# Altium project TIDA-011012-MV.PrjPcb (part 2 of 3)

## Sheet TIDA-011012-MV Communication.SchDoc
size 431 x 279 mm; Date: Not shown in title block; ApprovedBy: Not shown in title block; CheckedBy: Not shown in title block; Author: Not shown in title block; CompanyName: Not shown in title block; Engineer: Not shown in title block; Organization: Not shown in title block; Address1: Not shown in title block; Address2: Not shown in title block; Address3: Not shown in title block; Address4: Not shown in title block; DocumentNumber: 3; Revision: Use project parameter SCH_Rev; SheetNumber: 3; SheetTotal: 11; PageSetup: Record=PageOptions¦CenterHorizontal=True¦CenterVertical=True¦PrintScale=1.00¦XCorrection=1.00¦YCorrection=1.00¦PrintKind=0¦BorderSize=5000000¦LeftOffset=0¦BottomOffset=0¦Orientation=2¦PaperLength=1000¦PaperWidth=1000¦Scale=100¦PaperSource=15¦PrintQuality=600¦MediaType=1¦DitherType=10¦PaperKind=Letter¦PrintScaleMode=1
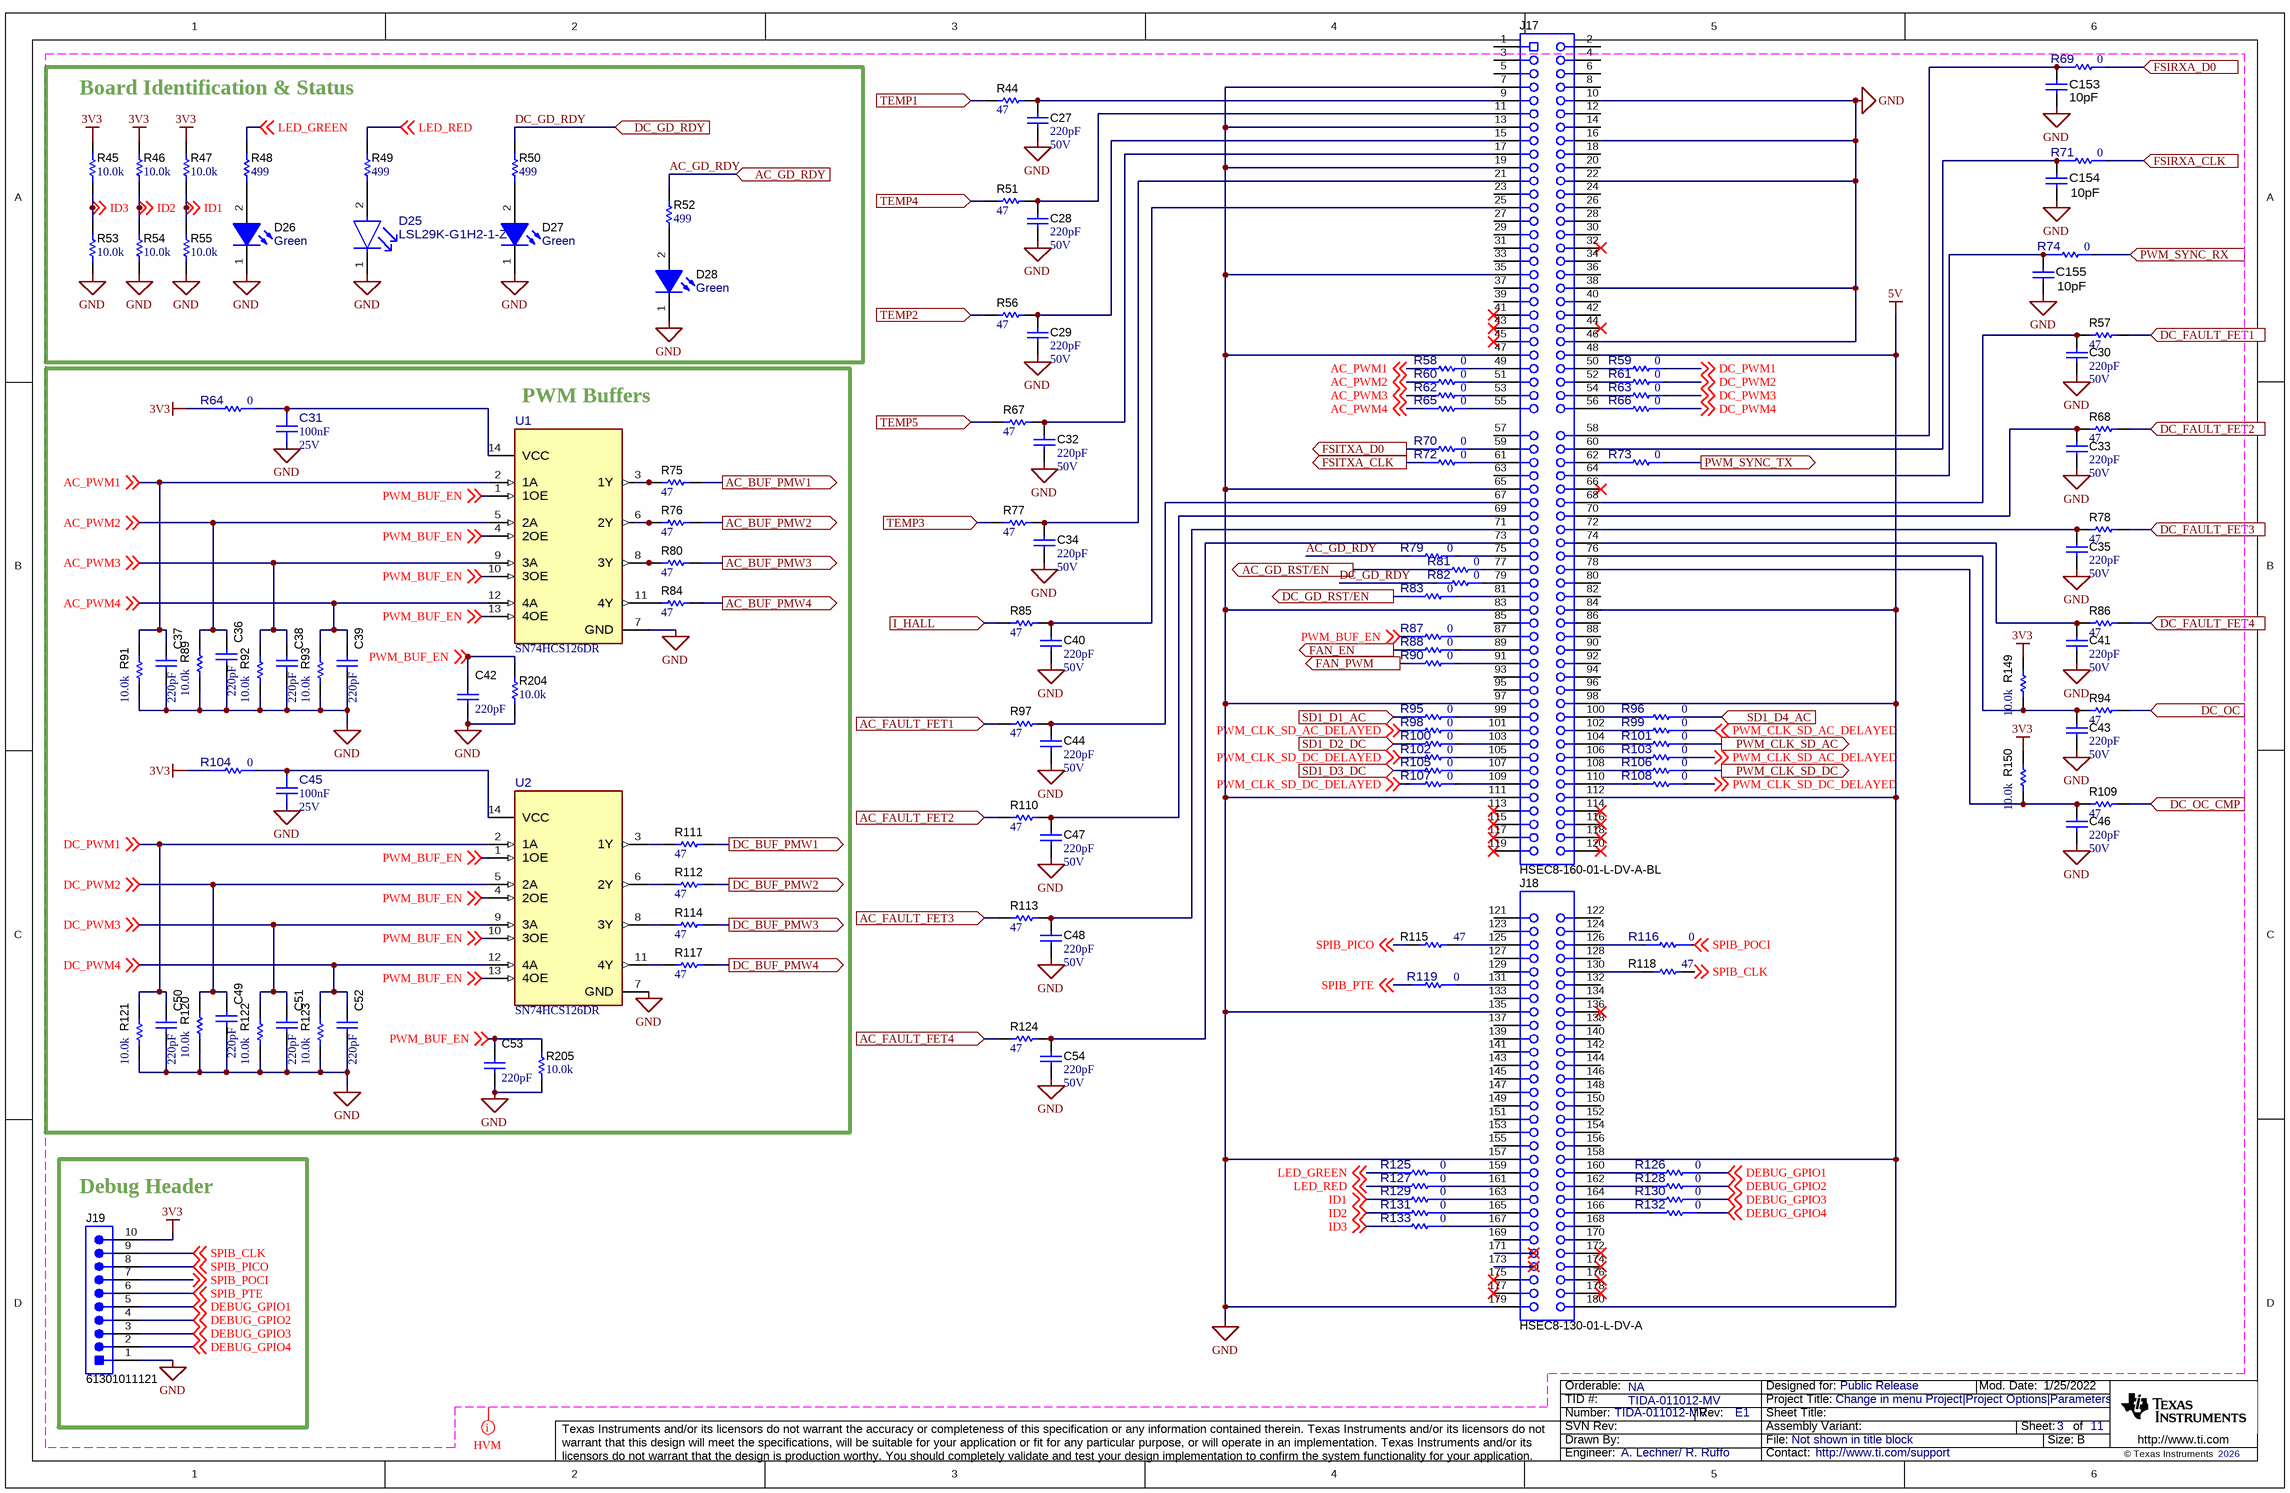
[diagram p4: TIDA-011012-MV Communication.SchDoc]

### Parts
C27  Cap_F: 220pF  VDC_V: 50V  [0603]  (hidden comment: C0603X221K5RACTU)
C28  Cap_F: 220pF  VDC_V: 50V  [0603]  (hidden comment: C0603X221K5RACTU)
C29  Cap_F: 220pF  VDC_V: 50V  [0603]  (hidden comment: C0603X221K5RACTU)
C30  Cap_F: 220pF  VDC_V: 50V  [0603]  (hidden comment: C0603X221K5RACTU)
C31  Cap_F: 100nF  VDC_V: 25V  [FP-GMC10X7R104K25NT_0603-MFG]  (hidden comment: GMC10X7R104K25NT)
C32  Cap_F: 220pF  VDC_V: 50V  [0603]  (hidden comment: C0603X221K5RACTU)
C33  Cap_F: 220pF  VDC_V: 50V  [0603]  (hidden comment: C0603X221K5RACTU)
C34  Cap_F: 220pF  VDC_V: 50V  [0603]  (hidden comment: C0603X221K5RACTU)
C35  Cap_F: 220pF  VDC_V: 50V  [0603]  (hidden comment: C0603X221K5RACTU)
C36  Cap_F: 220pF  [0603]  (hidden comment: C0603X221K5RACTU)
C37  Cap_F: 220pF  [0603]  (hidden comment: C0603X221K5RACTU)
C38  Cap_F: 220pF  [0603]  (hidden comment: C0603X221K5RACTU)
C39  Cap_F: 220pF  [0603]  (hidden comment: C0603X221K5RACTU)
C40  Cap_F: 220pF  VDC_V: 50V  [0603]  (hidden comment: C0603X221K5RACTU)
C41  Cap_F: 220pF  VDC_V: 50V  [0603]  (hidden comment: C0603X221K5RACTU)
C42  Cap_F: 220pF  [0603]  (hidden comment: C0603X221K5RACTU)
C43  Cap_F: 220pF  VDC_V: 50V  [0603]  (hidden comment: C0603X221K5RACTU)
C44  Cap_F: 220pF  VDC_V: 50V  [0603]  (hidden comment: C0603X221K5RACTU)
C45  Cap_F: 100nF  VDC_V: 25V  [FP-GMC10X7R104K25NT_0603-MFG]  (hidden comment: GMC10X7R104K25NT)
C46  Cap_F: 220pF  VDC_V: 50V  [0603]  (hidden comment: C0603X221K5RACTU)
C47  Cap_F: 220pF  VDC_V: 50V  [0603]  (hidden comment: C0603X221K5RACTU)
C48  Cap_F: 220pF  VDC_V: 50V  [0603]  (hidden comment: C0603X221K5RACTU)
C49  Cap_F: 220pF  [0603]  (hidden comment: C0603X221K5RACTU)
C50  Cap_F: 220pF  [0603]  (hidden comment: C0603X221K5RACTU)
C51  Cap_F: 220pF  [0603]  (hidden comment: C0603X221K5RACTU)
C52  Cap_F: 220pF  [0603]  (hidden comment: C0603X221K5RACTU)
C53  Cap_F: 220pF  [0603]  (hidden comment: C0603X221K5RACTU)
C54  Cap_F: 220pF  VDC_V: 50V  [0603]  (hidden comment: C0603X221K5RACTU)
C153  Cap_F: 10pF  [0603]  (hidden comment: 0603ZC100KAT2A)
C154  Cap_F: 10pF  [0603]  (hidden comment: 0603ZC100KAT2A)
C155  Cap_F: 10pF  [0603]  (hidden comment: 0603ZC100KAT2A)
D25  LSL29K-G1H2-1-Z  [FP-LSL29K-G1H2-1-Z_0603-0]
D26  value Green  [WL-SMCW_GREEN]  (hidden comment: 150060VS75000)
D27  value Green  [WL-SMCW_GREEN]  (hidden comment: 150060VS75000)
D28  value Green  [WL-SMCW_GREEN]  (hidden comment: 150060VS75000)
J17  HSEC8-160-01-L-DV-A-BL  [controlCARD-120HSEC]
J18  HSEC8-130-01-L-DV-A  [controlCARD-180HSEC-60pinAddon]
J19  61301011121  [Wurth_61301011121]
R44  ValueDisplayed: 47  [0603]  (hidden comment: ERJ-3GEYJ470V)
R45  ValueDisplayed: 10.0k  [0603]  (hidden comment: ERJ-3EKF1002V)
R46  ValueDisplayed: 10.0k  [0603]  (hidden comment: ERJ-3EKF1002V)
R47  ValueDisplayed: 10.0k  [0603]  (hidden comment: ERJ-3EKF1002V)
R48  ValueDisplayed: 499  [0603]  (hidden comment: CRCW0603499RFKEAC)
R49  ValueDisplayed: 499  [0603]  (hidden comment: CRCW0603499RFKEAC)
R50  ValueDisplayed: 499  [0603]  (hidden comment: CRCW0603499RFKEAC)
R51  ValueDisplayed: 47  [0603]  (hidden comment: ERJ-3GEYJ470V)
R52  ValueDisplayed: 499  [0603]  (hidden comment: CRCW0603499RFKEAC)
R53  ValueDisplayed: 10.0k  [0603]  (hidden comment: ERJ-3EKF1002V)
R54  ValueDisplayed: 10.0k  [0603]  (hidden comment: ERJ-3EKF1002V)
R55  ValueDisplayed: 10.0k  [0603]  (hidden comment: ERJ-3EKF1002V)
R56  ValueDisplayed: 47  [0603]  (hidden comment: ERJ-3GEYJ470V)
R57  ValueDisplayed: 47  [0603]  (hidden comment: ERJ-3GEYJ470V)
R58  value 0  [FP-ERJ-H3G0R00V_0603-MFG]  (hidden comment: ERJ-H3G0R00V)
R59  value 0  [FP-ERJ-H3G0R00V_0603-MFG]  (hidden comment: ERJ-H3G0R00V)
R60  value 0  [FP-ERJ-H3G0R00V_0603-MFG]  (hidden comment: ERJ-H3G0R00V)
R61  value 0  [FP-ERJ-H3G0R00V_0603-MFG]  (hidden comment: ERJ-H3G0R00V)
R62  value 0  [FP-ERJ-H3G0R00V_0603-MFG]  (hidden comment: ERJ-H3G0R00V)
R63  value 0  [FP-ERJ-H3G0R00V_0603-MFG]  (hidden comment: ERJ-H3G0R00V)
R64  value 0  [FP-ERJ-H3G0R00V_0603-MFG]  (hidden comment: ERJ-H3G0R00V)
R65  value 0  [FP-ERJ-H3G0R00V_0603-MFG]  (hidden comment: ERJ-H3G0R00V)
R66  value 0  [FP-ERJ-H3G0R00V_0603-MFG]  (hidden comment: ERJ-H3G0R00V)
R67  ValueDisplayed: 47  [0603]  (hidden comment: ERJ-3GEYJ470V)
R68  ValueDisplayed: 47  [0603]  (hidden comment: ERJ-3GEYJ470V)
R69  value 0  [FP-ERJ-H3G0R00V_0603-MFG]  (hidden comment: ERJ-H3G0R00V)
R70  value 0  [FP-ERJ-H3G0R00V_0603-MFG]  (hidden comment: ERJ-H3G0R00V)
R71  value 0  [FP-ERJ-H3G0R00V_0603-MFG]  (hidden comment: ERJ-H3G0R00V)
R72  value 0  [FP-ERJ-H3G0R00V_0603-MFG]  (hidden comment: ERJ-H3G0R00V)
R73  value 0  [FP-ERJ-H3G0R00V_0603-MFG]  (hidden comment: ERJ-H3G0R00V)
R74  value 0  [FP-ERJ-H3G0R00V_0603-MFG]  (hidden comment: ERJ-H3G0R00V)
R75  ValueDisplayed: 47  [0603]  (hidden comment: ERJ-3GEYJ470V)
R76  ValueDisplayed: 47  [0603]  (hidden comment: ERJ-3GEYJ470V)
R77  ValueDisplayed: 47  [0603]  (hidden comment: ERJ-3GEYJ470V)
R78  ValueDisplayed: 47  [0603]  (hidden comment: ERJ-3GEYJ470V)
R79  value 0  [FP-ERJ-H3G0R00V_0603-MFG]  (hidden comment: ERJ-H3G0R00V)
R80  ValueDisplayed: 47  [0603]  (hidden comment: ERJ-3GEYJ470V)
R81  value 0  [FP-ERJ-H3G0R00V_0603-MFG]  (hidden comment: ERJ-H3G0R00V)
R82  value 0  [FP-ERJ-H3G0R00V_0603-MFG]  (hidden comment: ERJ-H3G0R00V)
R83  value 0  [FP-ERJ-H3G0R00V_0603-MFG]  (hidden comment: ERJ-H3G0R00V)
R84  ValueDisplayed: 47  [0603]  (hidden comment: ERJ-3GEYJ470V)
R85  ValueDisplayed: 47  [0603]  (hidden comment: ERJ-3GEYJ470V)
R86  ValueDisplayed: 47  [0603]  (hidden comment: ERJ-3GEYJ470V)
R87  value 0  [FP-ERJ-H3G0R00V_0603-MFG]  (hidden comment: ERJ-H3G0R00V)
R88  value 0  [FP-ERJ-H3G0R00V_0603-MFG]  (hidden comment: ERJ-H3G0R00V)
R89  ValueDisplayed: 10.0k  [0603]  (hidden comment: ERJ-3EKF1002V)
R90  value 0  [FP-ERJ-H3G0R00V_0603-MFG]  (hidden comment: ERJ-H3G0R00V)
R91  ValueDisplayed: 10.0k  [0603]  (hidden comment: ERJ-3EKF1002V)
R92  ValueDisplayed: 10.0k  [0603]  (hidden comment: ERJ-3EKF1002V)
R93  ValueDisplayed: 10.0k  [0603]  (hidden comment: ERJ-3EKF1002V)
R94  ValueDisplayed: 47  [0603]  (hidden comment: ERJ-3GEYJ470V)
R95  value 0  [FP-ERJ-H3G0R00V_0603-MFG]  (hidden comment: ERJ-H3G0R00V)
R96  value 0  [FP-ERJ-H3G0R00V_0603-MFG]  (hidden comment: ERJ-H3G0R00V)
R97  ValueDisplayed: 47  [0603]  (hidden comment: ERJ-3GEYJ470V)
R98  value 0  [FP-ERJ-H3G0R00V_0603-MFG]  (hidden comment: ERJ-H3G0R00V)
R99  value 0  [FP-ERJ-H3G0R00V_0603-MFG]  (hidden comment: ERJ-H3G0R00V)
R100  value 0  [FP-ERJ-H3G0R00V_0603-MFG]  (hidden comment: ERJ-H3G0R00V)
R101  value 0  [FP-ERJ-H3G0R00V_0603-MFG]  (hidden comment: ERJ-H3G0R00V)
R102  value 0  [FP-ERJ-H3G0R00V_0603-MFG]  (hidden comment: ERJ-H3G0R00V)
R103  value 0  [FP-ERJ-H3G0R00V_0603-MFG]  (hidden comment: ERJ-H3G0R00V)
R104  value 0  [FP-ERJ-H3G0R00V_0603-MFG]  (hidden comment: ERJ-H3G0R00V)
R105  value 0  [FP-ERJ-H3G0R00V_0603-MFG]  (hidden comment: ERJ-H3G0R00V)
R106  value 0  [FP-ERJ-H3G0R00V_0603-MFG]  (hidden comment: ERJ-H3G0R00V)
R107  value 0  [FP-ERJ-H3G0R00V_0603-MFG]  (hidden comment: ERJ-H3G0R00V)
R108  value 0  [FP-ERJ-H3G0R00V_0603-MFG]  (hidden comment: ERJ-H3G0R00V)
R109  ValueDisplayed: 47  [0603]  (hidden comment: ERJ-3GEYJ470V)
R110  ValueDisplayed: 47  [0603]  (hidden comment: ERJ-3GEYJ470V)
R111  ValueDisplayed: 47  [0603]  (hidden comment: ERJ-3GEYJ470V)
R112  ValueDisplayed: 47  [0603]  (hidden comment: ERJ-3GEYJ470V)
R113  ValueDisplayed: 47  [0603]  (hidden comment: ERJ-3GEYJ470V)
R114  ValueDisplayed: 47  [0603]  (hidden comment: ERJ-3GEYJ470V)
R115  ValueDisplayed: 47  [0603]  (hidden comment: ERJ-3GEYJ470V)
R116  value 0  [FP-ERJ-H3G0R00V_0603-MFG]  (hidden comment: ERJ-H3G0R00V)
R117  ValueDisplayed: 47  [0603]  (hidden comment: ERJ-3GEYJ470V)
R118  ValueDisplayed: 47  [0603]  (hidden comment: ERJ-3GEYJ470V)
R119  value 0  [FP-ERJ-H3G0R00V_0603-IPC_B]  (hidden comment: ERJ-H3G0R00V)
R120  ValueDisplayed: 10.0k  [0603]  (hidden comment: ERJ-3EKF1002V)
R121  ValueDisplayed: 10.0k  [0603]  (hidden comment: ERJ-3EKF1002V)
R122  ValueDisplayed: 10.0k  [0603]  (hidden comment: ERJ-3EKF1002V)
R123  ValueDisplayed: 10.0k  [0603]  (hidden comment: ERJ-3EKF1002V)
R124  ValueDisplayed: 47  [0603]  (hidden comment: ERJ-3GEYJ470V)
R125  value 0  [FP-ERJ-H3G0R00V_0603-MFG]  (hidden comment: ERJ-H3G0R00V)
R126  value 0  [FP-ERJ-H3G0R00V_0603-MFG]  (hidden comment: ERJ-H3G0R00V)
R127  value 0  [FP-ERJ-H3G0R00V_0603-MFG]  (hidden comment: ERJ-H3G0R00V)
R128  value 0  [FP-ERJ-H3G0R00V_0603-MFG]  (hidden comment: ERJ-H3G0R00V)
R129  value 0  [FP-ERJ-H3G0R00V_0603-MFG]  (hidden comment: ERJ-H3G0R00V)
R130  value 0  [FP-ERJ-H3G0R00V_0603-MFG]  (hidden comment: ERJ-H3G0R00V)
R131  value 0  [FP-ERJ-H3G0R00V_0603-MFG]  (hidden comment: ERJ-H3G0R00V)
R132  value 0  [FP-ERJ-H3G0R00V_0603-MFG]  (hidden comment: ERJ-H3G0R00V)
R133  value 0  [FP-ERJ-H3G0R00V_0603-MFG]  (hidden comment: ERJ-H3G0R00V)
R149  ValueDisplayed: 10.0k  [0603]  (hidden comment: ERJ-3EKF1002V)
R150  ValueDisplayed: 10.0k  [0603]  (hidden comment: ERJ-3EKF1002V)
R204  ValueDisplayed: 10.0k  [0603]  (hidden comment: ERJ-3EKF1002V)
R205  ValueDisplayed: 10.0k  [0603]  (hidden comment: ERJ-3EKF1002V)
U1  SN74HCS126DR  [D0014A-MFG]
U2  SN74HCS126DR  [D0014A-MFG]

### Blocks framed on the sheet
Board Identification & Status: D25-D28 R45-R50 R52-R55
PWM Buffers: C31 C36-C39 C42 C45 C49-C53 R64 R75 R76 R80 R84 R89 R91-R93 R104 R111 R112 R114 R117 R120-R123 R204 R205 U1 U2
Debug Header: J19

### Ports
AC_BUF_PMW1 (out), AC_BUF_PMW2 (out), AC_BUF_PMW3 (out), AC_BUF_PMW4 (out), AC_FAULT_FET1 (in), AC_FAULT_FET2 (in), AC_FAULT_FET3 (in), AC_FAULT_FET4 (in), AC_GD_RDY (in), AC_GD_RST/EN (out), DC_BUF_PMW1 (out), DC_BUF_PMW2 (out), DC_BUF_PMW3 (out), DC_BUF_PMW4 (out), DC_FAULT_FET1 (in), DC_FAULT_FET2 (in), DC_FAULT_FET3 (in), DC_FAULT_FET4 (in), DC_GD_RDY (in), DC_GD_RST/EN (out), DC_OC (in), DC_OC_CMP (in), FAN_EN (out), FAN_PWM (out), FSIRXA_CLK (in), FSIRXA_D0 (in), FSITXA_CLK (out), FSITXA_D0 (out), I_HALL (in), PWM_CLK_SD_AC (out), PWM_CLK_SD_DC (out), PWM_SYNC_RX (in), PWM_SYNC_TX (out), SD1_D1_AC (in), SD1_D2_DC (in), SD1_D3_DC (in), SD1_D4_AC (in), TEMP1 (in), TEMP2 (in), TEMP3 (in), TEMP4 (in), TEMP5 (in)

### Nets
3V3: J19.10 R45.2 R46.2 R47.2 R64.1 R104.1 R149.2 R150.2
5V: J17.48 J17.84 J17.98 J17.112 J18.158 J18.180
GND: C27.2 C28.2 C29.2 C30.2 C31.1 C32.2 C33.2 C34.2 C35.2 C36.1 C37.1 C38.1 C39.1 C40.2 C41.2 C42.1 C43.2 C44.2 C45.1 C46.2 C47.2 C48.2 C49.1 C50.1 C51.1 C52.1 C53.1 C54.2 C153.2 C154.2 C155.2 D25.1(CATHODE) D26.1(K) D27.1(K) D28.1(K) J17.7 J17.10 J17.13 J17.16 J17.19 J17.22 J17.35 J17.38 J17.46 J17.47 J17.65 J17.83 J17.97 J17.111 J18.135 J18.157 J18.179 J19.1 R53.1 R54.1 R55.1 R89.1 R91.1 R92.1 R93.1 R120.1 R121.1 R122.1 R123.1 R204.1 R205.1 U1.7(GND) U2.7(GND)
AC_BUF_PMW1: R75.2 ; port AC_BUF_PMW1
AC_BUF_PMW2: R76.2 ; port AC_BUF_PMW2
AC_BUF_PMW3: R80.2 ; port AC_BUF_PMW3
AC_BUF_PMW4: R84.2 ; port AC_BUF_PMW4
AC_FAULT_FET1: R97.1 ; port AC_FAULT_FET1
AC_FAULT_FET2: R110.1 ; port AC_FAULT_FET2
AC_FAULT_FET3: R113.1 ; port AC_FAULT_FET3
AC_FAULT_FET4: R124.1 ; port AC_FAULT_FET4
AC_GD_RDY: R52.2 R79.1 ; port AC_GD_RDY
AC_GD_RST/EN: R81.1 ; port AC_GD_RST/EN
AC_PWM1: C37.2 R58.1 R91.2 U1.2(1A) ; off-sheet AC_PWM1
AC_PWM2: C36.2 R60.1 R89.2 U1.5(2A) ; off-sheet AC_PWM2
AC_PWM3: C38.2 R62.1 R92.2 U1.9(3A) ; off-sheet AC_PWM3
AC_PWM4: C39.2 R65.1 R93.2 U1.12(4A) ; off-sheet AC_PWM4
CLK_MOD_AC: R101.1 ; port PWM_CLK_SD_AC
CLK_MOD_DC: R106.1 ; port PWM_CLK_SD_DC
DATA_I_AC: R95.1 ; port SD1_D1_AC
DATA_I_DC: R100.1 ; port SD1_D2_DC
DATA_V_AC: R96.1 ; port SD1_D4_AC
DATA_V_DC: R105.1 ; port SD1_D3_DC
DC_BUF_PMW1: R111.2 ; port DC_BUF_PMW1
DC_BUF_PMW2: R112.2 ; port DC_BUF_PMW2
DC_BUF_PMW3: R114.2 ; port DC_BUF_PMW3
DC_BUF_PMW4: R117.2 ; port DC_BUF_PMW4
DC_FAULT_FET1: R57.2 ; port DC_FAULT_FET1
DC_FAULT_FET2: R68.2 ; port DC_FAULT_FET2
DC_FAULT_FET3: R78.2 ; port DC_FAULT_FET3
DC_FAULT_FET4: R86.2 ; port DC_FAULT_FET4
DC_GD_RDY: R50.2 R82.1 ; port DC_GD_RDY
DC_GD_RST/EN: R83.1 ; port DC_GD_RST/EN
DC_OC: R94.2 ; port DC_OC
DC_OC_CMP: R109.2 ; port DC_OC_CMP
DC_PWM1: C50.2 R59.2 R121.2 U2.2(1A) ; off-sheet DC_PWM1
DC_PWM2: C49.2 R61.2 R120.2 U2.5(2A) ; off-sheet DC_PWM2
DC_PWM3: C51.2 R63.2 R122.2 U2.9(3A) ; off-sheet DC_PWM3
DC_PWM4: C52.2 R66.2 R123.2 U2.12(4A) ; off-sheet DC_PWM4
DEBUG_GPIO1: J19.5 R126.1 ; off-sheet DEBUG_GPIO1
DEBUG_GPIO2: J19.4 R128.1 ; off-sheet DEBUG_GPIO2
DEBUG_GPIO3: J19.3 R130.1 ; off-sheet DEBUG_GPIO3
DEBUG_GPIO4: J19.2 R132.1 ; off-sheet DEBUG_GPIO4
FAN_EN: R88.1 ; port FAN_EN
FAN_PWM: R90.1 ; port FAN_PWM
FSIRXA_CLK: R71.2 ; port FSIRXA_CLK
FSIRXA_D0: R69.2 ; port FSIRXA_D0
FSITXA_CLK: R72.1 ; port FSITXA_CLK
FSITXA_D0: R70.1 ; port FSITXA_D0
I_HALL: R85.1 ; port I_HALL
ID1: R47.1 R55.2 R129.2 ; off-sheet ID1
ID2: R46.1 R54.2 R131.2 ; off-sheet ID2
ID3: R45.1 R53.2 R133.2 ; off-sheet ID3
LED_GREEN: R48.2 R125.2 ; off-sheet LED_GREEN
LED_RED: R49.2 R127.2 ; off-sheet LED_RED
PWM_BUF_EN: C42.2 C53.2 R87.1 R204.2 R205.2 U1.1(1OE) U1.4(2OE) U1.10(3OE) U1.13(4OE) U2.1(1OE) U2.4(2OE) U2.10(3OE) U2.13(4OE) ; off-sheet PWM_BUF_EN
PWM_CLK_SD_AC_DELAYED: R98.1 R99.1 R103.1 ; off-sheet PWM_CLK_SD_AC_DELAYED
PWM_CLK_SD_DC_DELAYED: R102.1 R107.1 R108.1 ; off-sheet PWM_CLK_SD_DC_DELAYED
PWM_SYNC_RX: R74.2 ; port PWM_SYNC_RX
PWM_SYNC_TX: R73.2 ; port PWM_SYNC_TX
SPIB_CLK: J19.9 R118.2 ; off-sheet SPIB_CLK
SPIB_PICO: J19.8 R115.1 ; off-sheet SPIB_PICO
SPIB_POCI: J19.7 R116.1 ; off-sheet SPIB_POCI
SPIB_PTE: J19.6 R119.2 ; off-sheet SPIB_PTE
TEMP1: R44.1 ; port TEMP1
TEMP2: R56.1 ; port TEMP2
TEMP3: R77.1 ; port TEMP3
TEMP4: R51.1 ; port TEMP4
TEMP5: R67.1 ; port TEMP5
NetC27_1: C27.1 J17.9 R44.2
NetC28_1: C28.1 J17.11 R51.2
NetC29_1: C29.1 J17.15 R56.2
NetC30_1: C30.1 J17.68 R57.1
NetC31_2: C31.2 R64.2 U1.14(VCC)
NetC32_1: C32.1 J17.17 R67.2
NetC33_1: C33.1 J17.70 R68.1
NetC34_1: C34.1 J17.21 R77.2
NetC35_1: C35.1 J17.72 R78.1
NetC40_1: C40.1 J17.25 R85.2
NetC41_1: C41.1 J17.74 R86.1
NetC43_1: C43.1 J17.76 R94.1 R149.1
NetC44_1: C44.1 J17.67 R97.2
NetC45_2: C45.2 R104.2 U2.14(VCC)
NetC46_1: C46.1 J17.78 R109.1 R150.1
NetC47_1: C47.1 J17.69 R110.2
NetC48_1: C48.1 J17.71 R113.2
NetC54_1: C54.1 J17.73 R124.2
NetC153_1: C153.1 J17.58 R69.1
NetC154_1: C154.1 J17.60 R71.1
NetC155_1: C155.1 J17.64 R74.1
NetD25_2: D25.2(ANODE) R49.1
NetD26_2: D26.2(A) R48.1
NetD27_2: D27.2(A) R50.1
NetD28_2: D28.2(A) R52.1
NetJ17_49: J17.49 R58.2
NetJ17_50: J17.50 R59.1
NetJ17_51: J17.51 R60.2
NetJ17_52: J17.52 R61.1
NetJ17_53: J17.53 R62.2
NetJ17_54: J17.54 R63.1
NetJ17_55: J17.55 R65.2
NetJ17_56: J17.56 R66.1
NetJ17_59: J17.59 R70.2
NetJ17_61: J17.61 R72.2
NetJ17_62: J17.62 R73.1
NetJ17_75: J17.75 R79.2
NetJ17_77: J17.77 R81.2
NetJ17_79: J17.79 R82.2
NetJ17_81: J17.81 R83.2
NetJ17_87: J17.87 R87.2
NetJ17_89: J17.89 R88.2
NetJ17_91: J17.91 R90.2
NetJ17_99: J17.99 R95.2
NetJ17_100: J17.100 R96.2
NetJ17_101: J17.101 R98.2
NetJ17_102: J17.102 R99.2
NetJ17_103: J17.103 R100.2
NetJ17_104: J17.104 R101.2
NetJ17_105: J17.105 R102.2
NetJ17_106: J17.106 R103.2
NetJ17_107: J17.107 R105.2
NetJ17_108: J17.108 R106.2
NetJ17_109: J17.109 R107.2
NetJ17_110: J17.110 R108.2
NetJ18_125: J18.125 R115.2
NetJ18_126: J18.126 R116.2
NetJ18_130: J18.130 R118.1
NetJ18_131: J18.131 R119.1
NetJ18_159: J18.159 R125.1
NetJ18_160: J18.160 R126.2
NetJ18_161: J18.161 R127.1
NetJ18_162: J18.162 R128.2
NetJ18_163: J18.163 R129.1
NetJ18_164: J18.164 R130.2
NetJ18_165: J18.165 R131.1
NetJ18_166: J18.166 R132.2
NetJ18_167: J18.167 R133.1
NetR75_1: R75.1 U1.3(1Y)
NetR76_1: R76.1 U1.6(2Y)
NetR80_1: R80.1 U1.8(3Y)
NetR84_1: R84.1 U1.11(4Y)
NetR111_1: R111.1 U2.3(1Y)
NetR112_1: R112.1 U2.6(2Y)
NetR114_1: R114.1 U2.8(3Y)
NetR117_1: R117.1 U2.11(4Y)

Not connected (* = marked no-connect by the designer): J17 1 2 3 4 5 6 8 12 14 18 20 23 24 26 27 28 29 30 31 32* 33 34 36 37 39 40 41* 42 43* 44* 45* 57 63 66* 80 82 85 86 88 90 92 93 94 95 96 113* 114* 115* 116* 117* 118* 119* 120*; J18 121 122 123 124 127 128 129 132 133 134 136* 137 138 139 140 141 142 143 144 145 146 147 148 149 150 151 152 153 154 155 156 168 169 170 171* 172* 173* 174* 175* 176* 177* 178*

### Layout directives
net class HVM: 3V3, 5V, AC_GD_RDY, AC_PWM1, AC_PWM2, AC_PWM3, AC_PWM4, DC_GD_RDY, DC_PWM1, DC_PWM2, DC_PWM3, DC_PWM4, DEBUG_GPIO1, DEBUG_GPIO2, DEBUG_GPIO3, DEBUG_GPIO4, GND, ID1, ID2, ID3, LED_GREEN, LED_RED, PWM_BUF_EN, PWM_CLK_SD_AC_DELAYED, PWM_CLK_SD_DC_DELAYED, SPIB_CLK, SPIB_PICO, SPIB_POCI, SPIB_PTE

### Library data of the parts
C27-C30 C32-C35 C40 C41 C43 C44 C46-C48 C54 = CMP-0006982-4: CAP, CERM, 220 pF, 50 V, +/- 10%, X7R, 0603; Manufacturer: Kemet; TaMin_C: -55°C; Polarized: N; SizeAreaWB_mm2: 4.68; Value1: Unknown; U/M: EA; Value: 220pF; TaMax_C: 125°C; SizeZ_mm: 1; SizeX_mm: 1.6; SizeY_mm: 0.8; SizeArea_mm2: 1.28; AEC Category: Q200
C31 C45 = CMP-0094950-1: 0.1 µF ±10% 25V Ceramic Capacitor X7R 0603 (1608 Metric); Manufacturer: CAL-CHIP ELECTRONICS; AEC Qualified: No; SizeZ_mm: 1mm; Value: 100nF; ValueDisplayed: 0.1uF; TempCo: 30ppm/°C
C36-C39 C42 C49-C53 = CMP-0006982-4: CAP, CERM, 220 pF, 50 V, +/- 10%, X7R, 0603; Manufacturer: Kemet; TaMin_C: -55°C; Polarized: N; SizeAreaWB_mm2: 4.68; Value1: Unknown; U/M: EA; Value: 220pF; TaMax_C: 125°C; SizeZ_mm: 1; SizeX_mm: 1.6; SizeY_mm: 0.8; Value2: 50V; SizeArea_mm2: 1.28; AEC Category: Q200
C153-C155 = CMP-0006811-4: CAP, CERM, 10 pF, 10 V, +/- 10%, X7R, 0603; Manufacturer: AVX; TaMin_C: -55°C; Polarized: N; SizeAreaWB_mm2: 4.68; Value1: Unknown; U/M: EA; Value: 10pF; TaMax_C: 125°C; SizeZ_mm: 1; SizeX_mm: 1.6; SizeY_mm: 0.8; Value2: 10V; SizeArea_mm2: 1.28; AEC Category: Q200
D25 = CMP-0092845-1: LED Uni-Color Red 643nm 2-Pin Chip 0603(1608Metric) T/R; Manufacturer: OSRAM Opto Semiconductors; AEC Grade: Grade 2; LuminousFlux_PhiV: 8.1/16.1lm; Vf_V: 1.8V; Forward Current: 2mA; Led Orientation: Top View; SizeZ_mm: 0.67mm; AEC Qualified: Yes; Luminous Intensity: 1.8-2.24/3.55-4.5mcd; Vr_V: 12V; Angle: 160°; LambdaD: 630nm; Tjmax_C: 110°C
D26-D28 = CMP-0002894-2: LED, Green, SMD; Manufacturer: Wurth Elektronik; Type: AlInGaP; Value2: 2V; Io_A: 20mA; Value1: W
J17 = CMP-0003814-2: C2000 controlCARD-120HSEC connector, SMT; Manufacturer: Samtec; Note: The pin numbering does not match Samtec datasheet
J18 = CMP-0003859-2: C2000 controlCARD-180HSEC (60-pin addon) connector, SMT; Manufacturer: Samtec; Note: The pin numbering does not match Samtec datasheet
J19 = CMP-0054804-1: Header, 2.54mm, 10x1, Gold, TH; Manufacturer: Wurth Elektronik; CNHeader: TRUE; Shrouded: N; Gender: Male; Row_Count: 1; Pitch_mm: 2.54; CT: FALSE
R44 R51 R56 R57 R67 R68 R75-R78 R80 R84-R86 R94 R97 R109-R115 R117 R118 R124 = CMP-0025880-3: RES, 47, 5%, 0.1 W, AEC-Q200 Grade 0, 0603; Manufacturer: Panasonic; Power_W: 100mW; TempCo: 200 ppm/C; Value_Code: 47R0; U/M: EA; Value: 47; EIA_Code: E24; SizeX_mm: 1.6; SizeY_mm: 0.8; SizeZ_mm: 1; Value2: 0.1W; SizeArea_mm2: 1.28; AEC Qualified: Y; AEC Grade: 0; AEC Category: Q200
R45-R47 R53-R55 R89 R91-R93 R120-R123 R149 R150 R204 R205 = CMP-0022684-3: RES, 10.0 k, 1%, 0.1 W, 0603; Manufacturer: Panasonic; Power_W: 100mW; TempCo: 100 ppm/C; Value_Code: 10k0; U/M: EA; Value: 10.0k; EIA_Code: E96; Res_ohm: 10k; SizeX_mm: 1.6; SizeY_mm: 0.8; SizeZ_mm: 1; Value2: 0.1W; SizeArea_mm2: 1.28; VDC_V: 75V; AEC Category: Q200
R48-R50 R52 = CMP-0082532-1: RES, 499, 1%, 0.1 W, 0603; Manufacturer: Vishay-Dale; Power_W: 100mW; TempCo: 100 ppm/C; SizeAreaWB_mm2: 4.68; Value_Code: 499R; Value: 499; EIA_Code: E96; SizeX_mm: 1.6; SizeY_mm: 0.8; SizeZ_mm: 1; Value2: 0.1W; SizeArea_mm2: 1.28; AEC Qualified: N; VDC_V: 75V; AEC Category: Q200
R58-R66 R69-R74 R79 R81-R83 R87 R88 R90 R95 R96 R98-R108 R116 R119 R125-R133 = CMP-0097467-1: 0 Ohms Jumper 0.125W, 1/8W Chip Resistor 0603 (1608 Metric) Automotive AEC-Q200 Thick Film; Manufacturer: Panasonic; VDC_V: 75V; Power_W: 125mW; AEC Qualified: Yes; SizeZ_mm: 0.55mm; AEC Grade: Grade 0
U1 U2 = CMP-0093039-1: Schmitt-trigger inputs quadruple bus buffer gates with 3-state outputs 14-SOIC -40 to 125; Manufacturer: Texas Instruments; Min Supply Voltage: 2V; TJmax_C: +150°C; Logic Function Desc: Non-Inverting; Number Of Inputs: 1; AEC Qualified: No; Max Supply Voltage: 6V; SizeZ_mm: 1.75mm; PositionCount: 4; TaMin_C: -40°C; Standoff Height: 0.1mm; Nominal Supply Current: 0.1uA; TaMax_C: +125°C; Propagation Delay: 7ns

## Sheet TIDA-011012-MV AC IV Sensing.SchDoc
size 431 x 279 mm; Date: Not shown in title block; ApprovedBy: Not shown in title block; CheckedBy: Not shown in title block; Author: Not shown in title block; CompanyName: Not shown in title block; Engineer: Not shown in title block; Organization: Not shown in title block; Address1: Not shown in title block; Address2: Not shown in title block; Address3: Not shown in title block; Address4: Not shown in title block; DocumentNumber: 7; Revision: Use project parameter SCH_Rev; SheetNumber: 7; SheetTotal: 11; PageSetup: Record=PageOptions¦CenterHorizontal=True¦CenterVertical=True¦PrintScale=1.00¦XCorrection=1.00¦YCorrection=1.00¦PrintKind=0¦BorderSize=5000000¦LeftOffset=0¦BottomOffset=0¦Orientation=2¦PaperLength=1000¦PaperWidth=1000¦Scale=100¦PaperSource=15¦PrintQuality=600¦MediaType=1¦DitherType=10¦PaperKind=Letter¦PrintScaleMode=1
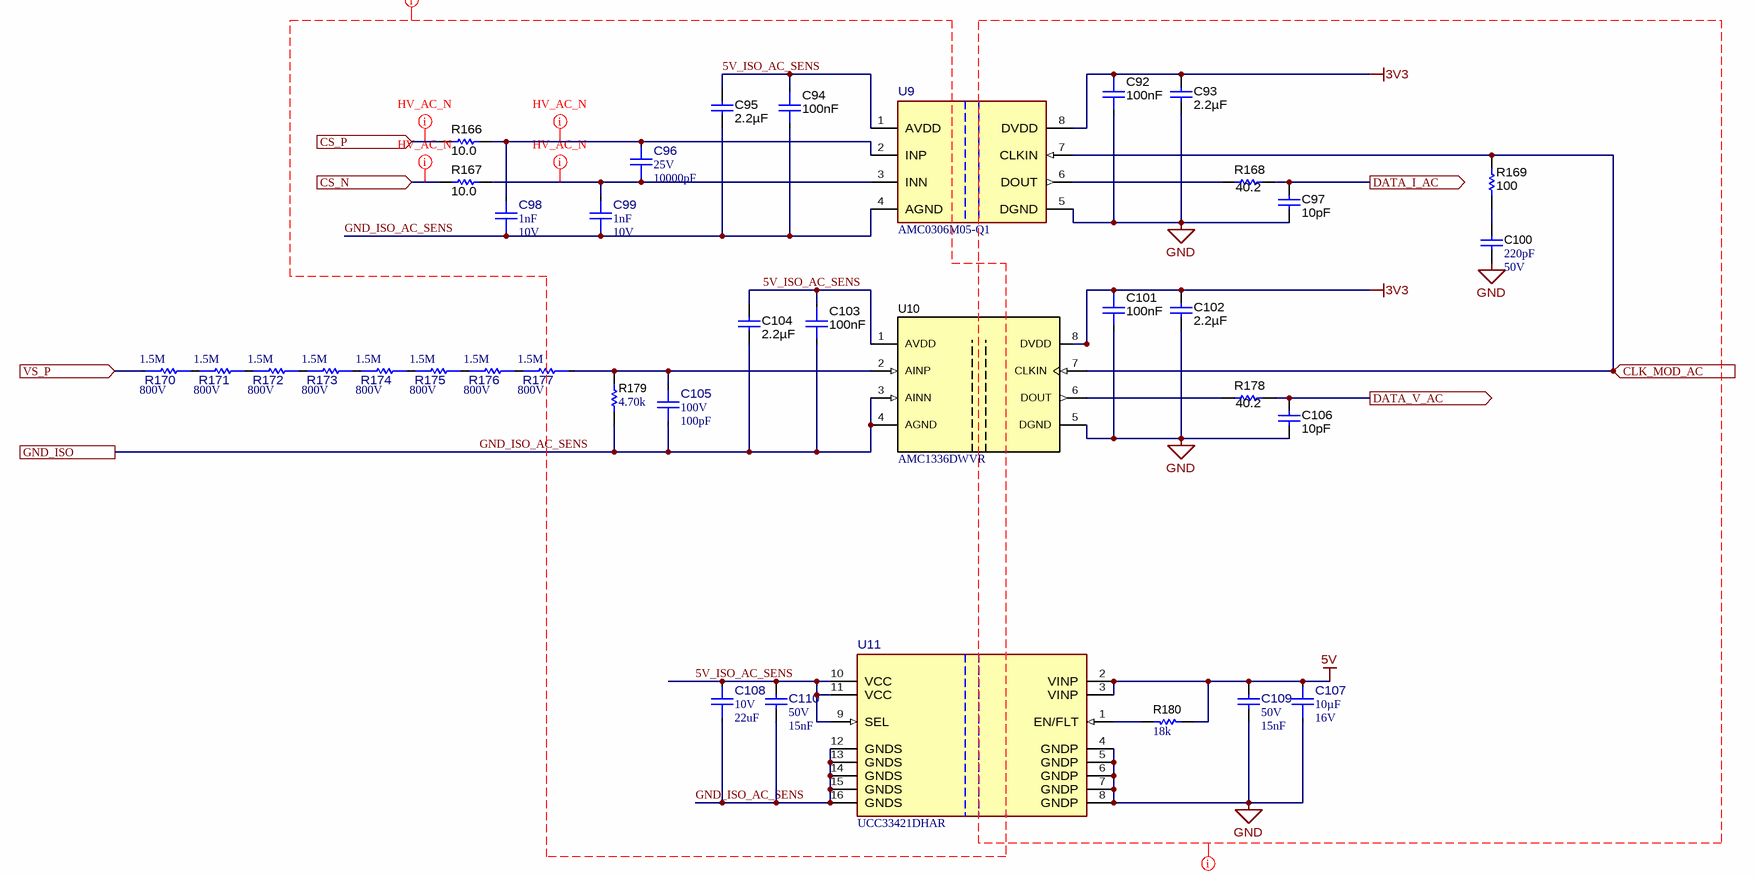
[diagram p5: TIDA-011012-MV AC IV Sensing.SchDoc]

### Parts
C92  Cap_F: 100nF  [FP-CL10B104KA8VPJC_0603-MFG]  (hidden comment: CL10B104KA8VPJC)
C93  Cap_F: 2.2µF  [0603]  (hidden comment: CC0603KRX7R7BB225)
C94  Cap_F: 100nF  [FP-CL10B104KA8VPJC_0603-MFG]  (hidden comment: CL10B104KA8VPJC)
C95  Cap_F: 2.2µF  [0603]  (hidden comment: CC0603KRX7R7BB225)
C96  VDC_V: 25V  ValueDisplayed: 10000pF  [FP-C0603C103J3GAC7867_0603-MFG]  (hidden comment: C0603C103J3GAC7867)
C97  Cap_F: 10pF  [0603]  (hidden comment: 0603ZC100KAT2A)
C98  Cap_F: 1nF  VDC_V: 10V  [FP-0603ZC102KAT2A_0603-MFG]  (hidden comment: 0603ZC102KAT2A)
C99  Cap_F: 1nF  VDC_V: 10V  [FP-0603ZC102KAT2A_0603-MFG]  (hidden comment: 0603ZC102KAT2A)
C100  Cap_F: 220pF  VDC_V: 50V  [0603]  (hidden comment: C0603X221K5RACTU)
C101  Cap_F: 100nF  [FP-CL10B104KA8VPJC_0603-MFG]  (hidden comment: CL10B104KA8VPJC)
C102  Cap_F: 2.2µF  [0603]  (hidden comment: CC0603KRX7R7BB225)
C103  Cap_F: 100nF  [FP-CL10B104KA8VPJC_0603-MFG]  (hidden comment: CL10B104KA8VPJC)
C104  Cap_F: 2.2µF  [0603]  (hidden comment: CC0603KRX7R7BB225)
C105  VDC_V: 100V  Cap_F: 100pF  [FP-06031C101JAT2A_0603-MFG]  (hidden comment: 06031C101JAT2A)
C106  Cap_F: 10pF  [0603]  (hidden comment: 0603ZC100KAT2A)
C107  Cap_F: 10µF  VDC_V: 16V  [FP-MA0805XR106K160_0805-IPC_C]  (hidden comment: MA0805XR106K160)
C108  VDC_V: 10V  ValueDisplayed: 22uF  [FP-GRT21BD71A226ME13L_0805-MFG]  (hidden comment: GRT21BD71A226ME13L)
C109  VDC_V: 50V  Cap_F: 15nF  [FP-C0603C153K5RACTU_0603-IPC_A]  (hidden comment: C0603C153K5RACTU)
C110  VDC_V: 50V  Cap_F: 15nF  [FP-C0603C153K5RACTU_0603-IPC_A]  (hidden comment: C0603C153K5RACTU)
R166  ValueDisplayed: 10.0  [0603]  (hidden comment: TNPW060310R0BEEA)
R167  ValueDisplayed: 10.0  [0603]  (hidden comment: TNPW060310R0BEEA)
R168  ValueDisplayed: 40.2  [0603]  (hidden comment: RC0603FR-0740R2L)
R169  ValueDisplayed: 100  [0603]  (hidden comment: RC0603FR-07100RL)
R170  value 1.5M  VDC_V: 800V  [FP-CHV1206-FX-1504ELF_1206-MFG]  (hidden comment: CHV1206-FX-1504ELF)
R171  value 1.5M  VDC_V: 800V  [FP-CHV1206-FX-1504ELF_1206-MFG]  (hidden comment: CHV1206-FX-1504ELF)
R172  value 1.5M  VDC_V: 800V  [FP-CHV1206-FX-1504ELF_1206-MFG]  (hidden comment: CHV1206-FX-1504ELF)
R173  value 1.5M  VDC_V: 800V  [FP-CHV1206-FX-1504ELF_1206-MFG]  (hidden comment: CHV1206-FX-1504ELF)
R174  value 1.5M  VDC_V: 800V  [FP-CHV1206-FX-1504ELF_1206-MFG]  (hidden comment: CHV1206-FX-1504ELF)
R175  value 1.5M  VDC_V: 800V  [FP-CHV1206-FX-1504ELF_1206-MFG]  (hidden comment: CHV1206-FX-1504ELF)
R176  value 1.5M  VDC_V: 800V  [FP-CHV1206-FX-1504ELF_1206-MFG]  (hidden comment: CHV1206-FX-1504ELF)
R177  value 1.5M  VDC_V: 800V  [FP-CHV1206-FX-1504ELF_1206-MFG]  (hidden comment: CHV1206-FX-1504ELF)
R178  ValueDisplayed: 40.2  [0603]  (hidden comment: RC0603FR-0740R2L)
R179  ValueDisplayed: 4.70k  [0603]  (hidden comment: RC0603FR-074K7L)
R180  ValueDisplayed: 18k  [0603]  (hidden comment: RC0603JR-0718KL)
U9  AMC0306M05-Q1  [DWV0008A-MFG]
U10  AMC1336DWVR  [DWV0008A]
U11  UCC33421DHAR  [DHA0016A-MFG]

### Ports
CLK_MOD_AC (in), CS_N (in), CS_P (in), DATA_I_AC (out), DATA_V_AC (out), GND_ISO, VS_P (in)

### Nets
3V3: C92.1 C93.1 C101.1 C102.1 U9.8(DVDD) U10.8(DVDD)
5V: C107.2 C109.1 R180.2 U11.2(VINP) U11.3(VINP)
GND: C92.2 C93.2 C97.2 C100.2 C101.2 C102.2 C106.2 C107.1 C109.2 U9.5(DGND) U10.5(DGND) U11.4(GNDP) U11.5(GNDP) U11.6(GNDP) U11.7(GNDP) U11.8(GNDP)
5V_ISO_AC_SENS: C94.1 C95.1 C103.1 C104.1 C108.2 C110.1 U9.1(AVDD) U10.1(AVDD) U11.9(SEL) U11.10(VCC) U11.11(VCC)
CLK_MOD_AC: R169.2 U9.7(CLKIN) U10.7(CLKIN) ; port CLK_MOD_AC
DATA_I_AC: C97.1 R168.2 ; port DATA_I_AC
DATA_V_AC: C106.1 R178.2 ; port DATA_V_AC
GND_ISO_AC_SENS: C94.2 C95.2 C98.1 C99.1 C103.2 C104.2 C105.1 C108.1 C110.2 R179.1 U9.4(AGND) U10.3(AINN) U10.4(AGND) U11.12(GNDS) U11.13(GNDS) U11.14(GNDS) U11.15(GNDS) U11.16(GNDS) ; port GND_ISO
IAC_NEG: R167.1 ; port CS_N
IAC_POS: R166.1 ; port CS_P
VAC_POS: R170.1 ; port VS_P
NetC96_1: C96.1 C99.2 R167.2 U9.3(INN)
NetC96_2: C96.2 C98.2 R166.2 U9.2(INP)
NetC100_1: C100.1 R169.1
NetC105_2: C105.2 R177.2 R179.2 U10.2(AINP)
NetR168_1: R168.1 U9.6(DOUT)
NetR170_2: R170.2 R171.1
NetR171_2: R171.2 R172.1
NetR172_2: R172.2 R173.1
NetR173_2: R173.2 R174.1
NetR174_2: R174.2 R175.1
NetR175_2: R175.2 R176.1
NetR176_2: R176.2 R177.1
NetR178_1: R178.1 U10.6(DOUT)
NetR180_1: R180.1 U11.1(EN/FLT)

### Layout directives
net class HV_AC_N: 5V_ISO_AC_SENS, GND_ISO_AC_SENS, IAC_NEG, IAC_POS, NetC96_1, NetC96_2
net class HVM: 3V3, 5V, GND

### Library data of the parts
C92 C94 C101 C103 = CMP-0121051-1: Automotive CAP, 100㎋, 25V, ±10%, X7R, 0603, 5mm Bending; Manufacturer: Samsung; AEC Grade: Grade 1; AEC Qualified: Yes; SizeZ_mm: 0.9mm; TempCo: 15%; Value: 100nF
C93 C95 C102 C104 = CMP-0079605-1: CAP, CERM, 2.2 µF, 16 V,+/- 10%, X7R, 0603; Manufacturer: Yageo America; TaMin_C: -55°C; Polarized: N; SizeAreaWB_mm2: 4.68; U/M: EA; Value: 2.2uF; TaMax_C: 125°C; SizeZ_mm: 1; SizeX_mm: 1.6; SizeY_mm: 0.8; Value2: 16V; SizeArea_mm2: 1.28; AEC Category: Q200
C96 = CMP-0095473-1: 10000 pF ±5% 25V Ceramic Capacitor C0G, NP0 0603 (1608 Metric); Manufacturer: KEMET; Cap_F: 10nF; SizeZ_mm: 0.87mm; TempCo: 30ppm/°C; Value: 10nF; AEC Qualified: No
C97 C106 = CMP-0006811-4: as C153-C155 on sheet TIDA-011012-MV Communication
C98 C99 = CMP-0120686-1: 1000 pF ±10% 10V Ceramic Capacitor X7R 0603 (1608 Metric); Manufacturer: KYOCERA AVX; AEC Qualified: No; SizeZ_mm: 0.9mm; TempCo: 15%; Value: 1nF
C100 = CMP-0006982-4: as C27 on sheet TIDA-011012-MV Communication
C105 = CMP-0096605-1: 100 pF ±5% 100V Ceramic Capacitor X7R 0603 (1608 Metric); Manufacturer: KYOCERA AVX; TempCo: 15%; AEC Qualified: No; SizeZ_mm: 0.9mm; Value: 100pF
C107 = CMP-0121624-1: 10 µF ±10% 16V Ceramic Capacitor X7R 0805 (2012 Metric); Manufacturer: Meritek; AEC Qualified: No; SizeZ_mm: 1.45mm; TempCo: 15%; ValueDisplayed: 10uF; Value: 10µF
C108 = CMP-0095621-1: 22μF ±20% 10V Ceramic Capacitor X7T 0805 (2012 Metric); Manufacturer: Murata; AEC Qualified: Yes; SizeZ_mm: 1.45mm; TempCo: +22/-33%; AEC Grade: Grade 1
C109 C110 = CMP-0086419-2: Cap Ceramic 0.015uF 50V X7R 10% Pad SMD 0603 125°C T/R; Manufacturer: Kemet; SizeZ_mm: 0.87mm; AEC Qualified: No; TempCo: 15%; Symbol Name: SYM-C0603C153K5RACTU
R166 R167 = CMP-0025687-2: RES, 10.0, 0.1%, 0.1 W, 0603; Manufacturer: Vishay-Dale; Power_W: 100mW; TempCo: 25 ppm/C; Value_Code: 10R0; U/M: EA; Value: 10.0; EIA_Code: E192; Res_ohm: 10; SizeX_mm: 1.6; SizeY_mm: 0.8; SizeZ_mm: 1; Value2: 0.1W; SizeArea_mm2: 1.28; VDC_V: 75V; AEC Category: Q200
R168 R178 = CMP-0023099-5: RES, 40.2, 1%, 0.1 W, 0603; Manufacturer: Yageo; Power_W: 100mW; TempCo: 100 ppm/C; Value_Code: 40R2; Value: 40.2; EIA_Code: E96; SizeX_mm: 1.6; SizeY_mm: 0.8; SizeZ_mm: 1; Value2: 0.1W; SizeArea_mm2: 1.28; AEC Qualified: N; VDC_V: 75V; AEC Category: Q200; SizeAreaWB_mm2: 4.68
R169 = CMP-0022736-4: RES, 100, 1%, 0.1 W, 0603; Manufacturer: Yageo; Power_W: 100mW; TempCo: 100 ppm/C; Value_Code: 100R; Value: 100; EIA_Code: E96; SizeX_mm: 1.6; SizeY_mm: 0.8; SizeZ_mm: 1; Value2: 0.1W; SizeArea_mm2: 1.28; AEC Qualified: N; VDC_V: 75V; AEC Category: Q200; SizeAreaWB_mm2: 4.68
R170-R177 = CMP-0120473-1: Thick Film High Voltage Chip Resistors 1206 1.5MOhm ±1% ±100ppm/°C; Manufacturer: Bourns; AEC Qualified: No; Power_W: 250mW; SizeZ_mm: 0.65mm
R179 = CMP-0023153-5: RES, 4.70 k, 1%, 0.1 W, 0603; Manufacturer: Yageo; Power_W: 100mW; TempCo: 100 ppm/C; Value_Code: 4k70; Value: 4.70k; Res_ohm: 4.7k; SizeX_mm: 1.6; SizeY_mm: 0.8; SizeZ_mm: 1; Value2: 0.1W; SizeArea_mm2: 1.28; AEC Qualified: N; VDC_V: 75V; AEC Category: Q200; SizeAreaWB_mm2: 4.68
R180 = CMP-0025892-5: RES, 18 k, 5%, 0.1 W, 0603; Manufacturer: Yageo; Power_W: 100mW; TempCo: 100 ppm/C; Value_Code: 18k0; Value: 18k; EIA_Code: E24; SizeX_mm: 1.6; SizeY_mm: 0.8; SizeZ_mm: 1; Value2: 0.1W; SizeArea_mm2: 1.28; AEC Qualified: N; VDC_V: 75V; AEC Category: Q200; SizeAreaWB_mm2: 4.68
U9 = CMP-0125127-1: Automotive, Precision, ±250-mV Input Isolated Delta-Sigma Modulators With External Clock; Manufacturer: Texas Instruments; SizeZ_mm: 2.8mm; AEC Qualified: Yes; AEC Grade: Grade 1; Max Supply Voltage: 5.5V; Min Supply Voltage: 2.7V; Standoff Height: 0.36mm; TaMax_C: +125°C; TaMin_C: -40°C; TJmax_C: +150°C
U10 = CMP-0860008-1: AMC1336 Small, High-Precision, Reinforced Isolated Delta-Sigma Modulator With Input Optimized for Voltage Sensing Applications, DWV0008A (SOIC-8); Manufacturer: Texas Instruments; AEC Qualified: N; AEC Category: Q200; SizeY_mm: 5.85; SizeX_mm: 11.5; SizeAreaWB_mm2: 105.975; SizeArea_mm2: 67.275; CompType: IC; SizeZ_mm: 2.8
U11 = CMP-0123146-1: Ultra-Small, 1.5W, 5.0V, 5kVRMS Isolation, Industrial DC/DC Module; Manufacturer: Texas Instruments; SizeZ_mm: 2.6mm; AEC Qualified: No; Max Supply Voltage: 5.5V; Min Supply Voltage: 4.5V; Nominal Supply Current: 7-545mA; Number Of Outputs: 1; Output Type: AdjustableProgrammable; Output Voltage: 5/5.5V; Standoff Height: 0.1mm; Switching Frequency: 76MHz; Switching Topology: Boost; TaMax_C: +125°C; TaMin_C: -40°C; TJmax_C: +150°C

## Sheet TIDA-011012-MV DC IV Sensing.SchDoc
size 431 x 279 mm; Date: Not shown in title block; ApprovedBy: Not shown in title block; CheckedBy: Not shown in title block; Author: Not shown in title block; CompanyName: Not shown in title block; Engineer: Not shown in title block; Organization: Not shown in title block; Address1: Not shown in title block; Address2: Not shown in title block; Address3: Not shown in title block; Address4: Not shown in title block; DocumentNumber: 6; Revision: Use project parameter SCH_Rev; SheetNumber: 6; SheetTotal: 11; PageSetup: Record=PageOptions¦CenterHorizontal=True¦CenterVertical=True¦PrintScale=1.00¦XCorrection=1.00¦YCorrection=1.00¦PrintKind=0¦BorderSize=5000000¦LeftOffset=0¦BottomOffset=0¦Orientation=2¦PaperLength=1000¦PaperWidth=1000¦Scale=100¦PaperSource=15¦PrintQuality=600¦MediaType=1¦DitherType=10¦PaperKind=Letter¦PrintScaleMode=1
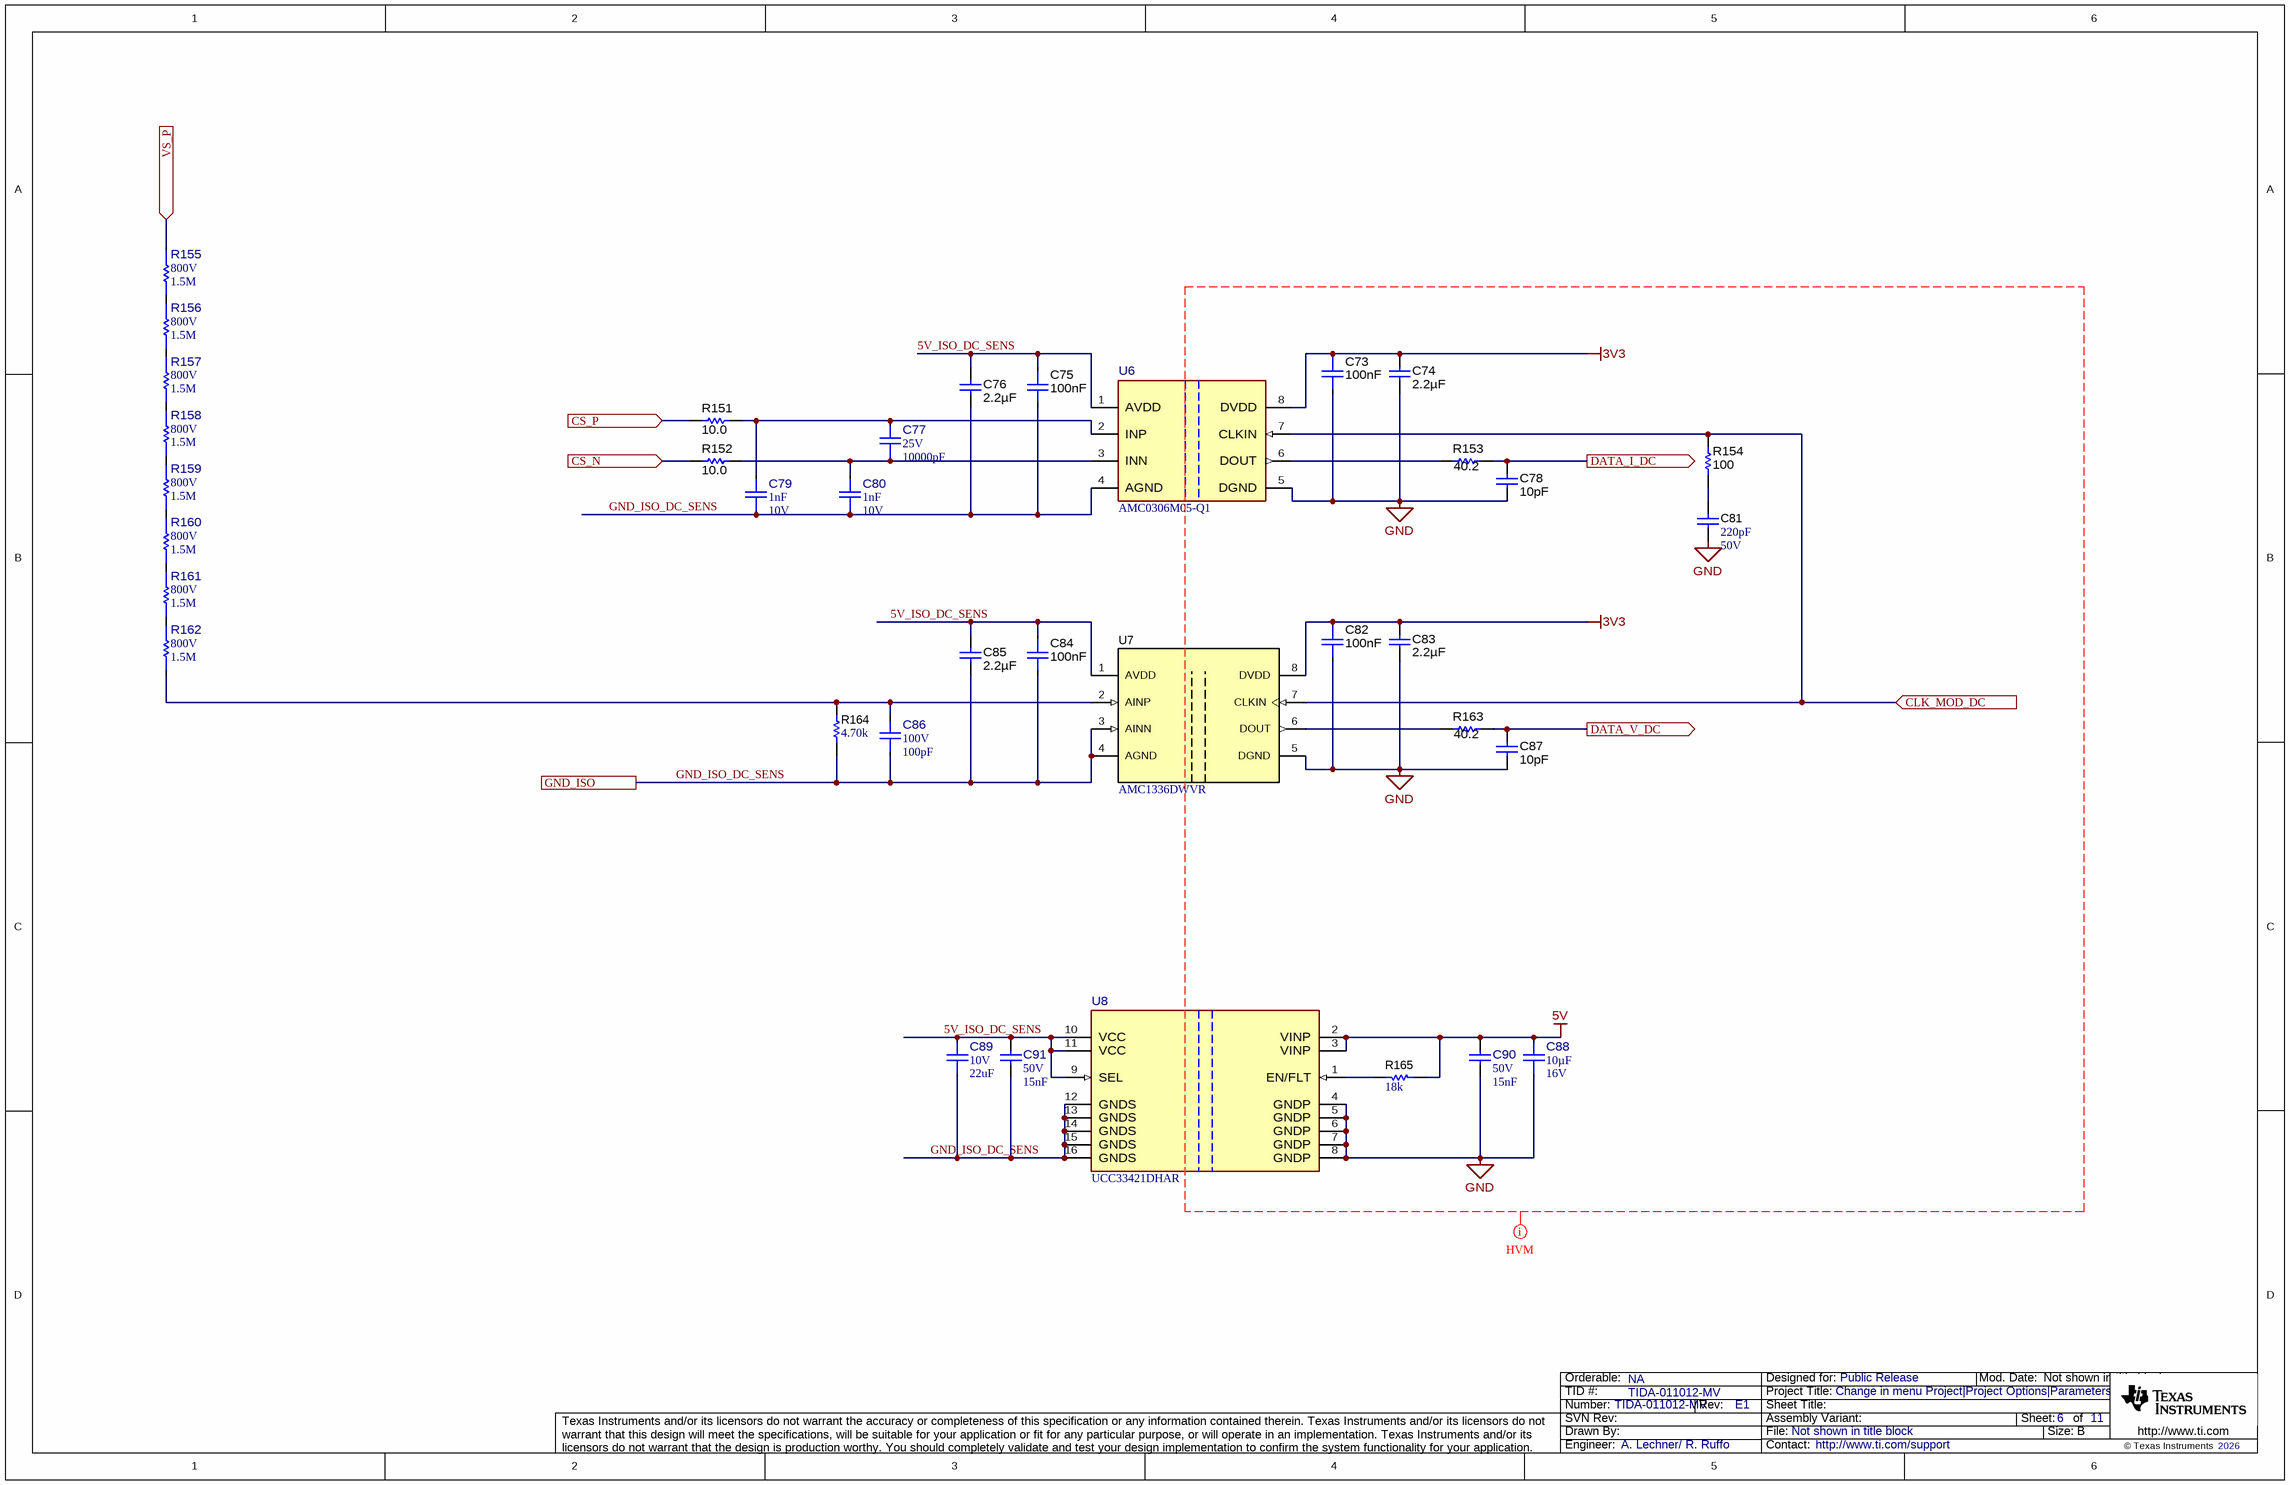
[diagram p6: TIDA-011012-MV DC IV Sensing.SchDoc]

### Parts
C73  Cap_F: 100nF  [FP-CL10B104KA8VPJC_0603-MFG]  (hidden comment: CL10B104KA8VPJC)
C74  Cap_F: 2.2µF  [0603]  (hidden comment: CC0603KRX7R7BB225)
C75  Cap_F: 100nF  [FP-CL10B104KA8VPJC_0603-MFG]  (hidden comment: CL10B104KA8VPJC)
C76  Cap_F: 2.2µF  [0603]  (hidden comment: CC0603KRX7R7BB225)
C77  VDC_V: 25V  ValueDisplayed: 10000pF  [FP-C0603C103J3GAC7867_0603-MFG]  (hidden comment: C0603C103J3GAC7867)
C78  Cap_F: 10pF  [0603]  (hidden comment: 0603ZC100KAT2A)
C79  Cap_F: 1nF  VDC_V: 10V  [FP-0603ZC102KAT2A_0603-MFG]  (hidden comment: 0603ZC102KAT2A)
C80  Cap_F: 1nF  VDC_V: 10V  [FP-0603ZC102KAT2A_0603-MFG]  (hidden comment: 0603ZC102KAT2A)
C81  Cap_F: 220pF  VDC_V: 50V  [0603]  (hidden comment: C0603X221K5RACTU)
C82  Cap_F: 100nF  [FP-CL10B104KA8VPJC_0603-MFG]  (hidden comment: CL10B104KA8VPJC)
C83  Cap_F: 2.2µF  [0603]  (hidden comment: CC0603KRX7R7BB225)
C84  Cap_F: 100nF  [FP-CL10B104KA8VPJC_0603-MFG]  (hidden comment: CL10B104KA8VPJC)
C85  Cap_F: 2.2µF  [0603]  (hidden comment: CC0603KRX7R7BB225)
C86  VDC_V: 100V  Cap_F: 100pF  [FP-06031C101JAT2A_0603-MFG]  (hidden comment: 06031C101JAT2A)
C87  Cap_F: 10pF  [0603]  (hidden comment: 0603ZC100KAT2A)
C88  Cap_F: 10µF  VDC_V: 16V  [FP-MA0805XR106K160_0805-IPC_C]  (hidden comment: MA0805XR106K160)
C89  VDC_V: 10V  ValueDisplayed: 22uF  [FP-GRT21BD71A226ME13L_0805-MFG]  (hidden comment: GRT21BD71A226ME13L)
C90  VDC_V: 50V  Cap_F: 15nF  [FP-C0603C153K5RACTU_0603-IPC_A]  (hidden comment: C0603C153K5RACTU)
C91  VDC_V: 50V  Cap_F: 15nF  [FP-C0603C153K5RACTU_0603-IPC_A]  (hidden comment: C0603C153K5RACTU)
R151  ValueDisplayed: 10.0  [0603]  (hidden comment: TNPW060310R0BEEA)
R152  ValueDisplayed: 10.0  [0603]  (hidden comment: TNPW060310R0BEEA)
R153  ValueDisplayed: 40.2  [0603]  (hidden comment: RC0603FR-0740R2L)
R154  ValueDisplayed: 100  [0603]  (hidden comment: RC0603FR-07100RL)
R155  value 1.5M  VDC_V: 800V  [FP-CHV1206-FX-1504ELF_1206-MFG]  (hidden comment: CHV1206-FX-1504ELF)
R156  value 1.5M  VDC_V: 800V  [FP-CHV1206-FX-1504ELF_1206-MFG]  (hidden comment: CHV1206-FX-1504ELF)
R157  value 1.5M  VDC_V: 800V  [FP-CHV1206-FX-1504ELF_1206-MFG]  (hidden comment: CHV1206-FX-1504ELF)
R158  value 1.5M  VDC_V: 800V  [FP-CHV1206-FX-1504ELF_1206-MFG]  (hidden comment: CHV1206-FX-1504ELF)
R159  value 1.5M  VDC_V: 800V  [FP-CHV1206-FX-1504ELF_1206-MFG]  (hidden comment: CHV1206-FX-1504ELF)
R160  value 1.5M  VDC_V: 800V  [FP-CHV1206-FX-1504ELF_1206-MFG]  (hidden comment: CHV1206-FX-1504ELF)
R161  value 1.5M  VDC_V: 800V  [FP-CHV1206-FX-1504ELF_1206-MFG]  (hidden comment: CHV1206-FX-1504ELF)
R162  value 1.5M  VDC_V: 800V  [FP-CHV1206-FX-1504ELF_1206-MFG]  (hidden comment: CHV1206-FX-1504ELF)
R163  ValueDisplayed: 40.2  [0603]  (hidden comment: RC0603FR-0740R2L)
R164  ValueDisplayed: 4.70k  [0603]  (hidden comment: RC0603FR-074K7L)
R165  ValueDisplayed: 18k  [0603]  (hidden comment: RC0603JR-0718KL)
U6  AMC0306M05-Q1  [DWV0008A-MFG]
U7  AMC1336DWVR  [DWV0008A]
U8  UCC33421DHAR  [DHA0016A-MFG]

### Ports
CLK_MOD_DC (in), CS_N (in), CS_P (in), DATA_I_DC (out), DATA_V_DC (out), GND_ISO, VS_P (in)

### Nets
3V3: C73.1 C74.1 C82.1 C83.1 U6.8(DVDD) U7.8(DVDD)
5V: C88.2 C90.1 R165.2 U8.2(VINP) U8.3(VINP)
GND: C73.2 C74.2 C78.2 C81.2 C82.2 C83.2 C87.2 C88.1 C90.2 U6.5(DGND) U7.5(DGND) U8.4(GNDP) U8.5(GNDP) U8.6(GNDP) U8.7(GNDP) U8.8(GNDP)
5V_ISO_DC_SENS: C75.1 C76.1 C84.1 C85.1 C89.2 C91.1 U6.1(AVDD) U7.1(AVDD) U8.9(SEL) U8.10(VCC) U8.11(VCC)
CLK_MOD_DC: R154.2 U6.7(CLKIN) U7.7(CLKIN) ; port CLK_MOD_DC
DATA_I_DC: C78.1 R153.2 ; port DATA_I_DC
DATA_V_DC: C87.1 R163.2 ; port DATA_V_DC
DC_BUS_POS: R155.1 ; port VS_P
GND_ISO_DC_SENS: C75.2 C76.2 C79.1 C80.1 C84.2 C85.2 C86.1 C89.1 C91.2 R164.1 U6.4(AGND) U7.3(AINN) U7.4(AGND) U8.12(GNDS) U8.13(GNDS) U8.14(GNDS) U8.15(GNDS) U8.16(GNDS) ; port GND_ISO  [project net DC_BUS_DAB]
I_DC_MINUS: R152.1 ; port CS_N
I_DC_POS: R151.1 ; port CS_P
NetC77_1: C77.1 C80.2 R152.2 U6.3(INN)
NetC77_2: C77.2 C79.2 R151.2 U6.2(INP)
NetC81_1: C81.1 R154.1
NetC86_2: C86.2 R162.2 R164.2 U7.2(AINP)
NetR153_1: R153.1 U6.6(DOUT)
NetR155_2: R155.2 R156.1
NetR156_2: R156.2 R157.1
NetR157_2: R157.2 R158.1
NetR158_2: R158.2 R159.1
NetR159_2: R159.2 R160.1
NetR160_2: R160.2 R161.1
NetR161_2: R161.2 R162.1
NetR163_1: R163.1 U7.6(DOUT)
NetR165_1: R165.1 U8.1(EN/FLT)

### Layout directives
net class HVM: 3V3, 5V, GND

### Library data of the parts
C73 C75 C82 C84 = CMP-0121051-1: as C92 on sheet TIDA-011012-MV AC IV Sensing
C74 C76 C83 C85 = CMP-0079605-1: as C93 on sheet TIDA-011012-MV AC IV Sensing
C77 = CMP-0095473-1: as C96 on sheet TIDA-011012-MV AC IV Sensing
C78 C87 = CMP-0006811-4: as C153-C155 on sheet TIDA-011012-MV Communication
C79 C80 = CMP-0120686-1: as C98 on sheet TIDA-011012-MV AC IV Sensing
C81 = CMP-0006982-4: as C27 on sheet TIDA-011012-MV Communication
C86 = CMP-0096605-1: as C105 on sheet TIDA-011012-MV AC IV Sensing
C88 = CMP-0121624-1: as C107 on sheet TIDA-011012-MV AC IV Sensing
C89 = CMP-0095621-1: as C108 on sheet TIDA-011012-MV AC IV Sensing
C90 C91 = CMP-0086419-2: as C109 on sheet TIDA-011012-MV AC IV Sensing
R151 R152 = CMP-0025687-2: as R166 on sheet TIDA-011012-MV AC IV Sensing
R153 R163 = CMP-0023099-5: as R168 on sheet TIDA-011012-MV AC IV Sensing
R154 = CMP-0022736-4: as R169 on sheet TIDA-011012-MV AC IV Sensing
R155-R162 = CMP-0120473-1: as R170 on sheet TIDA-011012-MV AC IV Sensing
R164 = CMP-0023153-5: as R179 on sheet TIDA-011012-MV AC IV Sensing
R165 = CMP-0025892-5: as R180 on sheet TIDA-011012-MV AC IV Sensing
U6 = CMP-0125127-1: as U9 on sheet TIDA-011012-MV AC IV Sensing
U7 = CMP-0860008-1: as U10 on sheet TIDA-011012-MV AC IV Sensing
U8 = CMP-0123146-1: as U11 on sheet TIDA-011012-MV AC IV Sensing

## Sheet TIDA-011012-MV Current Comparator.SchDoc
size 431 x 279 mm; Date: Not shown in title block; ApprovedBy: Not shown in title block; CheckedBy: Not shown in title block; Author: Not shown in title block; CompanyName: Not shown in title block; Engineer: Not shown in title block; Organization: Not shown in title block; Address1: Not shown in title block; Address2: Not shown in title block; Address3: Not shown in title block; Address4: Not shown in title block; DocumentNumber: 8; Revision: Use project parameter SCH_Rev; SheetNumber: 8; SheetTotal: 11; PageSetup: Record=PageOptions¦CenterHorizontal=True¦CenterVertical=True¦PrintScale=1.00¦XCorrection=1.00¦YCorrection=1.00¦PrintKind=0¦BorderSize=5000000¦LeftOffset=0¦BottomOffset=0¦Orientation=2¦PaperLength=1000¦PaperWidth=1000¦Scale=100¦PaperSource=15¦PrintQuality=600¦MediaType=1¦DitherType=10¦PaperKind=Letter¦PrintScaleMode=1
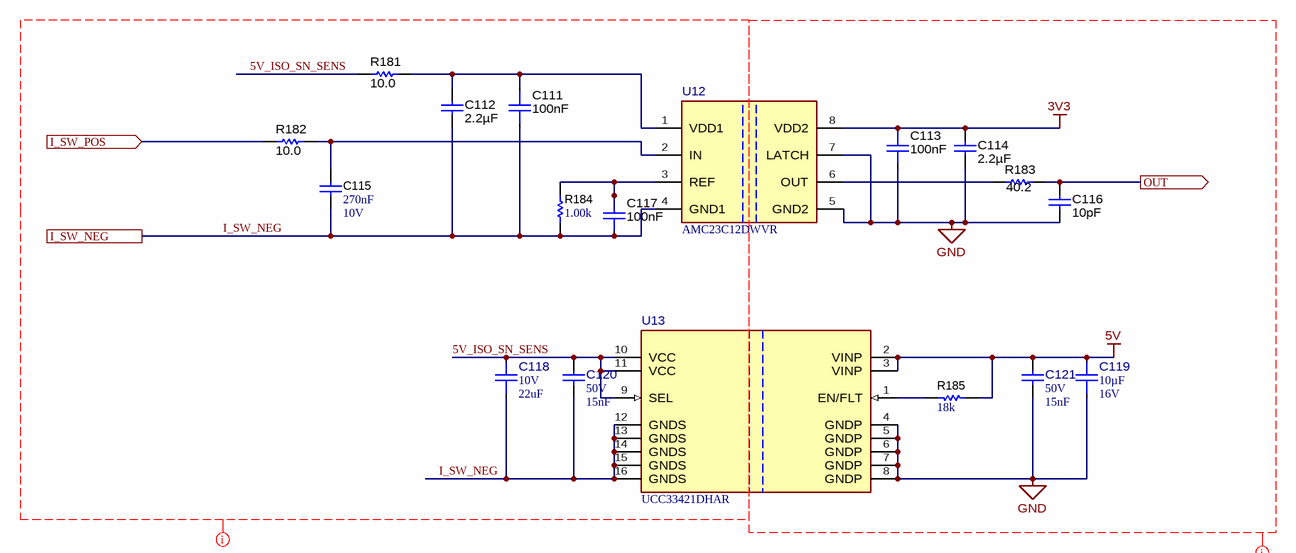
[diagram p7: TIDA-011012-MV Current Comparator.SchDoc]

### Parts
C111  Cap_F: 100nF  [FP-CL10B104KA8VPJC_0603-MFG]  (hidden comment: CL10B104KA8VPJC)
C112  Cap_F: 2.2µF  [0603]  (hidden comment: CC0603KRX7R7BB225)
C113  Cap_F: 100nF  [FP-CL10B104KA8VPJC_0603-MFG]  (hidden comment: CL10B104KA8VPJC)
C114  Cap_F: 2.2µF  [0603]  (hidden comment: CC0603KRX7R7BB225)
C115  Cap_F: 270nF  VDC_V: 10V  [0603]  (hidden comment: C0603C274K8RACTU)
C116  Cap_F: 10pF  [0603]  (hidden comment: 0603ZC100KAT2A)
C117  Cap_F: 100nF  [FP-CL10B104KA8VPJC_0603-MFG]  (hidden comment: CL10B104KA8VPJC)
C118  VDC_V: 10V  ValueDisplayed: 22uF  [FP-GRT21BD71A226ME13L_0805-MFG]  (hidden comment: GRT21BD71A226ME13L)
C119  Cap_F: 10µF  VDC_V: 16V  [FP-MA0805XR106K160_0805-IPC_C]  (hidden comment: MA0805XR106K160)
C120  VDC_V: 50V  Cap_F: 15nF  [FP-C0603C153K5RACTU_0603-IPC_A]  (hidden comment: C0603C153K5RACTU)
C121  VDC_V: 50V  Cap_F: 15nF  [FP-C0603C153K5RACTU_0603-IPC_A]  (hidden comment: C0603C153K5RACTU)
R181  ValueDisplayed: 10.0  [0603]  (hidden comment: TNPW060310R0BEEA)
R182  ValueDisplayed: 10.0  [0603]  (hidden comment: TNPW060310R0BEEA)
R183  ValueDisplayed: 40.2  [0603]  (hidden comment: RC0603FR-0740R2L)
R184  ValueDisplayed: 1.00k  [0603]  (hidden comment: ERJ-3EKF1001V)
R185  ValueDisplayed: 18k  [0603]  (hidden comment: RC0603JR-0718KL)
U12  AMC23C12DWVR  [DWV0008A-MFG]
U13  UCC33421DHAR  [DHA0016A-MFG]

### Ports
I_SW_NEG, I_SW_POS (in), OUT (out)

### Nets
3V3: C113.1 C114.1 U12.8(VDD2)
5V: C119.2 C121.1 R185.2 U13.2(VINP) U13.3(VINP)
GND: C113.2 C114.2 C116.2 C119.1 C121.2 U12.5(GND2) U12.7(LATCH) U13.4(GNDP) U13.5(GNDP) U13.6(GNDP) U13.7(GNDP) U13.8(GNDP)
5V_ISO_SN_SENS: C118.2 C120.1 R181.1 U13.9(SEL) U13.10(VCC) U13.11(VCC)
DC_OC_CMP: C116.1 R183.2 ; port OUT
I_SW_NEG: C111.2 C112.2 C115.2 C117.2 C118.1 C120.2 R184.1 U12.4(GND1) U13.12(GNDS) U13.13(GNDS) U13.14(GNDS) U13.15(GNDS) U13.16(GNDS) ; port I_SW_NEG
I_SW_POS: R182.1 ; port I_SW_POS
NetC111_1: C111.1 C112.1 R181.2 U12.1(VDD1)
NetC115_1: C115.1 R182.2 U12.2(IN)
NetC117_1: C117.1 R184.2 U12.3(REF)
NetR183_1: R183.1 U12.6(OUT)
NetR185_1: R185.1 U13.1(EN/FLT)

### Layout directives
net class HV_DC_SN_P: 5V_ISO_SN_SENS, I_SW_NEG
net class HVM: 3V3, 5V, GND

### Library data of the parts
C111 C113 C117 = CMP-0121051-1: as C92 on sheet TIDA-011012-MV AC IV Sensing
C112 C114 = CMP-0079605-1: as C93 on sheet TIDA-011012-MV AC IV Sensing
C115 = CMP-0006915-5: CAP, CERM, 0.27 uF, 10 V, +/- 10%, X7R, 0603; Manufacturer: Kemet; TaMin_C: -55°C; Polarized: N; SizeAreaWB_mm2: 4.68; Value1: Unknown; U/M: EA; Value: 0.27uF; TaMax_C: 125°C; SizeZ_mm: 1; SizeX_mm: 1.6; SizeY_mm: 0.8; SizeArea_mm2: 1.28; AEC Category: Q200
C116 = CMP-0006811-4: as C153-C155 on sheet TIDA-011012-MV Communication
C118 = CMP-0095621-1: as C108 on sheet TIDA-011012-MV AC IV Sensing
C119 = CMP-0121624-1: as C107 on sheet TIDA-011012-MV AC IV Sensing
C120 C121 = CMP-0086419-2: as C109 on sheet TIDA-011012-MV AC IV Sensing
R181 R182 = CMP-0025687-2: as R166 on sheet TIDA-011012-MV AC IV Sensing
R183 = CMP-0023099-5: as R168 on sheet TIDA-011012-MV AC IV Sensing
R184 = CMP-0022680-4: RES, 1.00 k, 1%, 0.1 W, 0603; Manufacturer: Panasonic; Power_W: 100mW; TempCo: 100 ppm/C; Value_Code: 1k00; U/M: EA; Value: 1.00k; EIA_Code: E96; Res_ohm: 1k; SizeX_mm: 1.6; SizeY_mm: 0.8; SizeZ_mm: 1; SizeArea_mm2: 1.28; VDC_V: 75V; AEC Category: Q200; Value2: 0.1W
R185 = CMP-0025892-5: as R180 on sheet TIDA-011012-MV AC IV Sensing
U12 = CMP-0092444-3: Dual, Fast Response, Reinforced Isolated Window Comparator with Adjustable Threshold; Manufacturer: Texas Instruments; AEC Category: Q200; CompType: IC; SizeZ_mm: 2.8mm; Standoff Height: 0.36mm; Number Of Channels: 2
U13 = CMP-0123146-1: as U11 on sheet TIDA-011012-MV AC IV Sensing

## Sheet TIDA-011012-MV Switch Node Hall Current Sensing.SchDoc
size 431 x 279 mm; Date: Not shown in title block; ApprovedBy: Not shown in title block; CheckedBy: Not shown in title block; Author: Not shown in title block; CompanyName: Not shown in title block; Engineer: Not shown in title block; Organization: Not shown in title block; Address1: Not shown in title block; Address2: Not shown in title block; Address3: Not shown in title block; Address4: Not shown in title block; DocumentNumber: 11; Revision: Use project parameter SCH_Rev; SheetNumber: 11; SheetTotal: 11; PageSetup: Record=PageOptions¦CenterHorizontal=True¦CenterVertical=True¦PrintScale=1.00¦XCorrection=1.00¦YCorrection=1.00¦PrintKind=0¦BorderSize=5000000¦LeftOffset=0¦BottomOffset=0¦Orientation=2¦PaperLength=1000¦PaperWidth=1000¦Scale=100¦PaperSource=15¦PrintQuality=600¦MediaType=1¦DitherType=10¦PaperKind=Letter¦PrintScaleMode=1
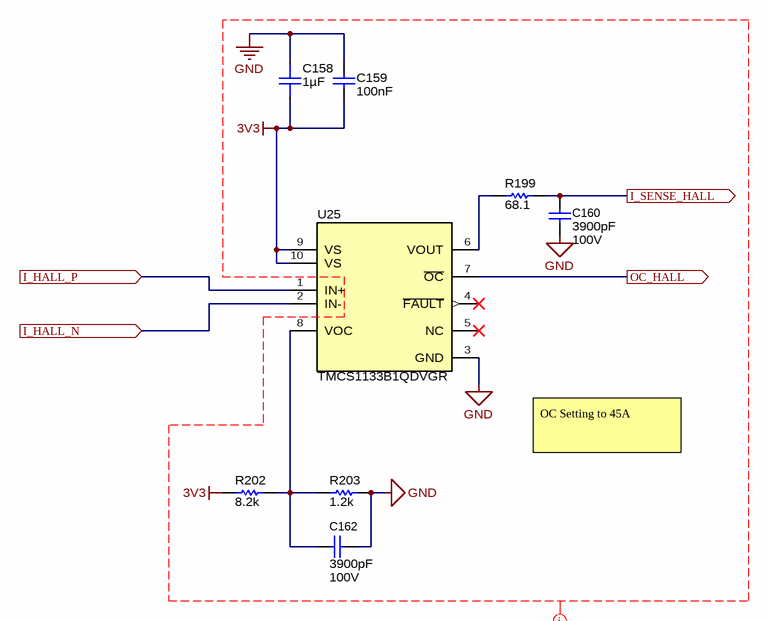
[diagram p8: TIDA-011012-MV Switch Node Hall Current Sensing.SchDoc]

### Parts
C158  Cap_F: 1µF  [FP-CL10B105KA8VPJC_0603-MFG]  (hidden comment: CL10B105KA8VPJC)
C159  Cap_F: 100nF  [0603]  (hidden comment: 06033C104KAT2A)
C160  ValueDisplayed: 3900pF  VDC_V: 100V  [0603]  (hidden comment: C1608C0G2A392J080AE)
C162  ValueDisplayed: 3900pF  VDC_V: 100V  [0603]  (hidden comment: C1608C0G2A392J080AE)
R199  ValueDisplayed: 68.1  [0603]  (hidden comment: CRCW060368R1FKEA)
R202  ValueDisplayed: 8.2k  [0603]  (hidden comment: RC0603JR-078K2L)
R203  ValueDisplayed: 1.2k  [0603]  (hidden comment: RC0603JR-071K2L)
U25  TMCS1133B1QDVGR  [DVG0010A-MFG]

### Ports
I_HALL_N (in), I_HALL_P (in), I_SENSE_HALL (out), OC_HALL (out)

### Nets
3V3: C158.2 C159.1 R202.1 U25.9(VS) U25.10(VS)
GND: C158.1 C159.2 C160.2 C162.2 R203.2 U25.3(GND)
DC_OC: U25.7(~{OC}) ; port OC_HALL
I_HALL: C160.1 R199.2 ; port I_SENSE_HALL
I_HALL_N: U25.2(IN-) ; port I_HALL_N
I_HALL_P: U25.1(IN+) ; port I_HALL_P
NetC162_1: C162.1 R202.2 R203.1 U25.8(VOC)
NetR199_1: R199.1 U25.6(VOUT)

Not connected (* = marked no-connect by the designer): U25 4(~{FAULT})* 5(NC)*

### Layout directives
net class HVM: 3V3, GND

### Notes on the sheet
- OC Setting to 45A

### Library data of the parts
C158 = CMP-0121052-1: Cap Ceramic 1uF 25V X7R ±10% Pad SMD 0603 +125°C T/R; Manufacturer: Samsung; AEC Grade: Grade 1; AEC Qualified: Yes; SizeZ_mm: 0.9mm; TempCo: 15%; Value: 1µF
C159 = CMP-0006753-4: CAP, CERM, 0.1 uF, 25 V, +/- 10%, X7R, 0603; Manufacturer: AVX; TaMin_C: -55°C; ESR_ohm: 0.05; Polarized: N; SizeAreaWB_mm2: 4.68; Value1: 0.05 ohm; U/M: EA; Value: 0.1uF; TaMax_C: 125°C; SizeZ_mm: 1; SizeX_mm: 1.6; SizeY_mm: 0.8; Value2: 25V; SizeArea_mm2: 1.28; AEC Category: Q200
C160 C162 = CMP-0860987-1: CAP, CERM, 3900 pF, 100 V,+/- 5%, C0G/NP0, 0603; Manufacturer: TDK; SizeArea_mm2: 1.28; SizeY_mm: 0.8; AEC Qualified: N; Cap_F: 3.9nF; Value: 3900pF; U/M: EA; AEC Category: Q200; SizeZ_mm: 1; TaMin_C: -55°C; TaMax_C: 125°C; SizeAreaWB_mm2: 4.68; SizeX_mm: 1.6
R199 = CMP-0022553-4: RES, 68.1, 1%, 0.1 W, AEC-Q200 Grade 0, 0603; Manufacturer: Vishay-Dale; Value: 68.1; Value_Code: 68R1; Power_W: 100mW; Value2: 0.1W; VDC_V: 75V; TempCo: 100 ppm/C; SizeArea_mm2: 1.28; SizeX_mm: 1.6; SizeY_mm: 0.8; SizeZ_mm: 1; EIA_Code: E96; AEC Category: Q200; AEC Qualified: Y; AEC Grade: 0
R202 = CMP-0025942-5: RES, 8.2 k, 5%, 0.1 W, 0603; Manufacturer: Yageo; Power_W: 100mW; TempCo: 100 ppm/C; Value_Code: 8k20; Value: 8.2k; EIA_Code: E24; SizeX_mm: 1.6; SizeY_mm: 0.8; SizeZ_mm: 1; Value2: 0.1W; SizeArea_mm2: 1.28; AEC Qualified: N; VDC_V: 75V; AEC Category: Q200; SizeAreaWB_mm2: 4.68
R203 = CMP-0025894-5: RES, 1.2 k, 5%, 0.1 W, 0603; Manufacturer: Yageo; Power_W: 100mW; TempCo: 100 ppm/C; Value_Code: 1k20; Value: 1.2k; EIA_Code: E24; SizeX_mm: 1.6; SizeY_mm: 0.8; SizeZ_mm: 1; Value2: 0.1W; SizeArea_mm2: 1.28; AEC Qualified: N; VDC_V: 75V; AEC Category: Q200; SizeAreaWB_mm2: 4.68
U25 = CMP-0097984-1: Manufacturer: Texas Instruments; Standoff Height: 0.1mm; SizeZ_mm: 2.65mm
